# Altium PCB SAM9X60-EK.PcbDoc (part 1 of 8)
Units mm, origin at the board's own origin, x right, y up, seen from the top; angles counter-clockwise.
Board outline 150 x 125 mm, 4 copper layers (L1 - Top Layer, L2 - GND, L3 - PWR, L4 - Bottom Layer), stack 1.52 mm thick; 566 components, 500 nets, 2132 pads, 1038 vias.
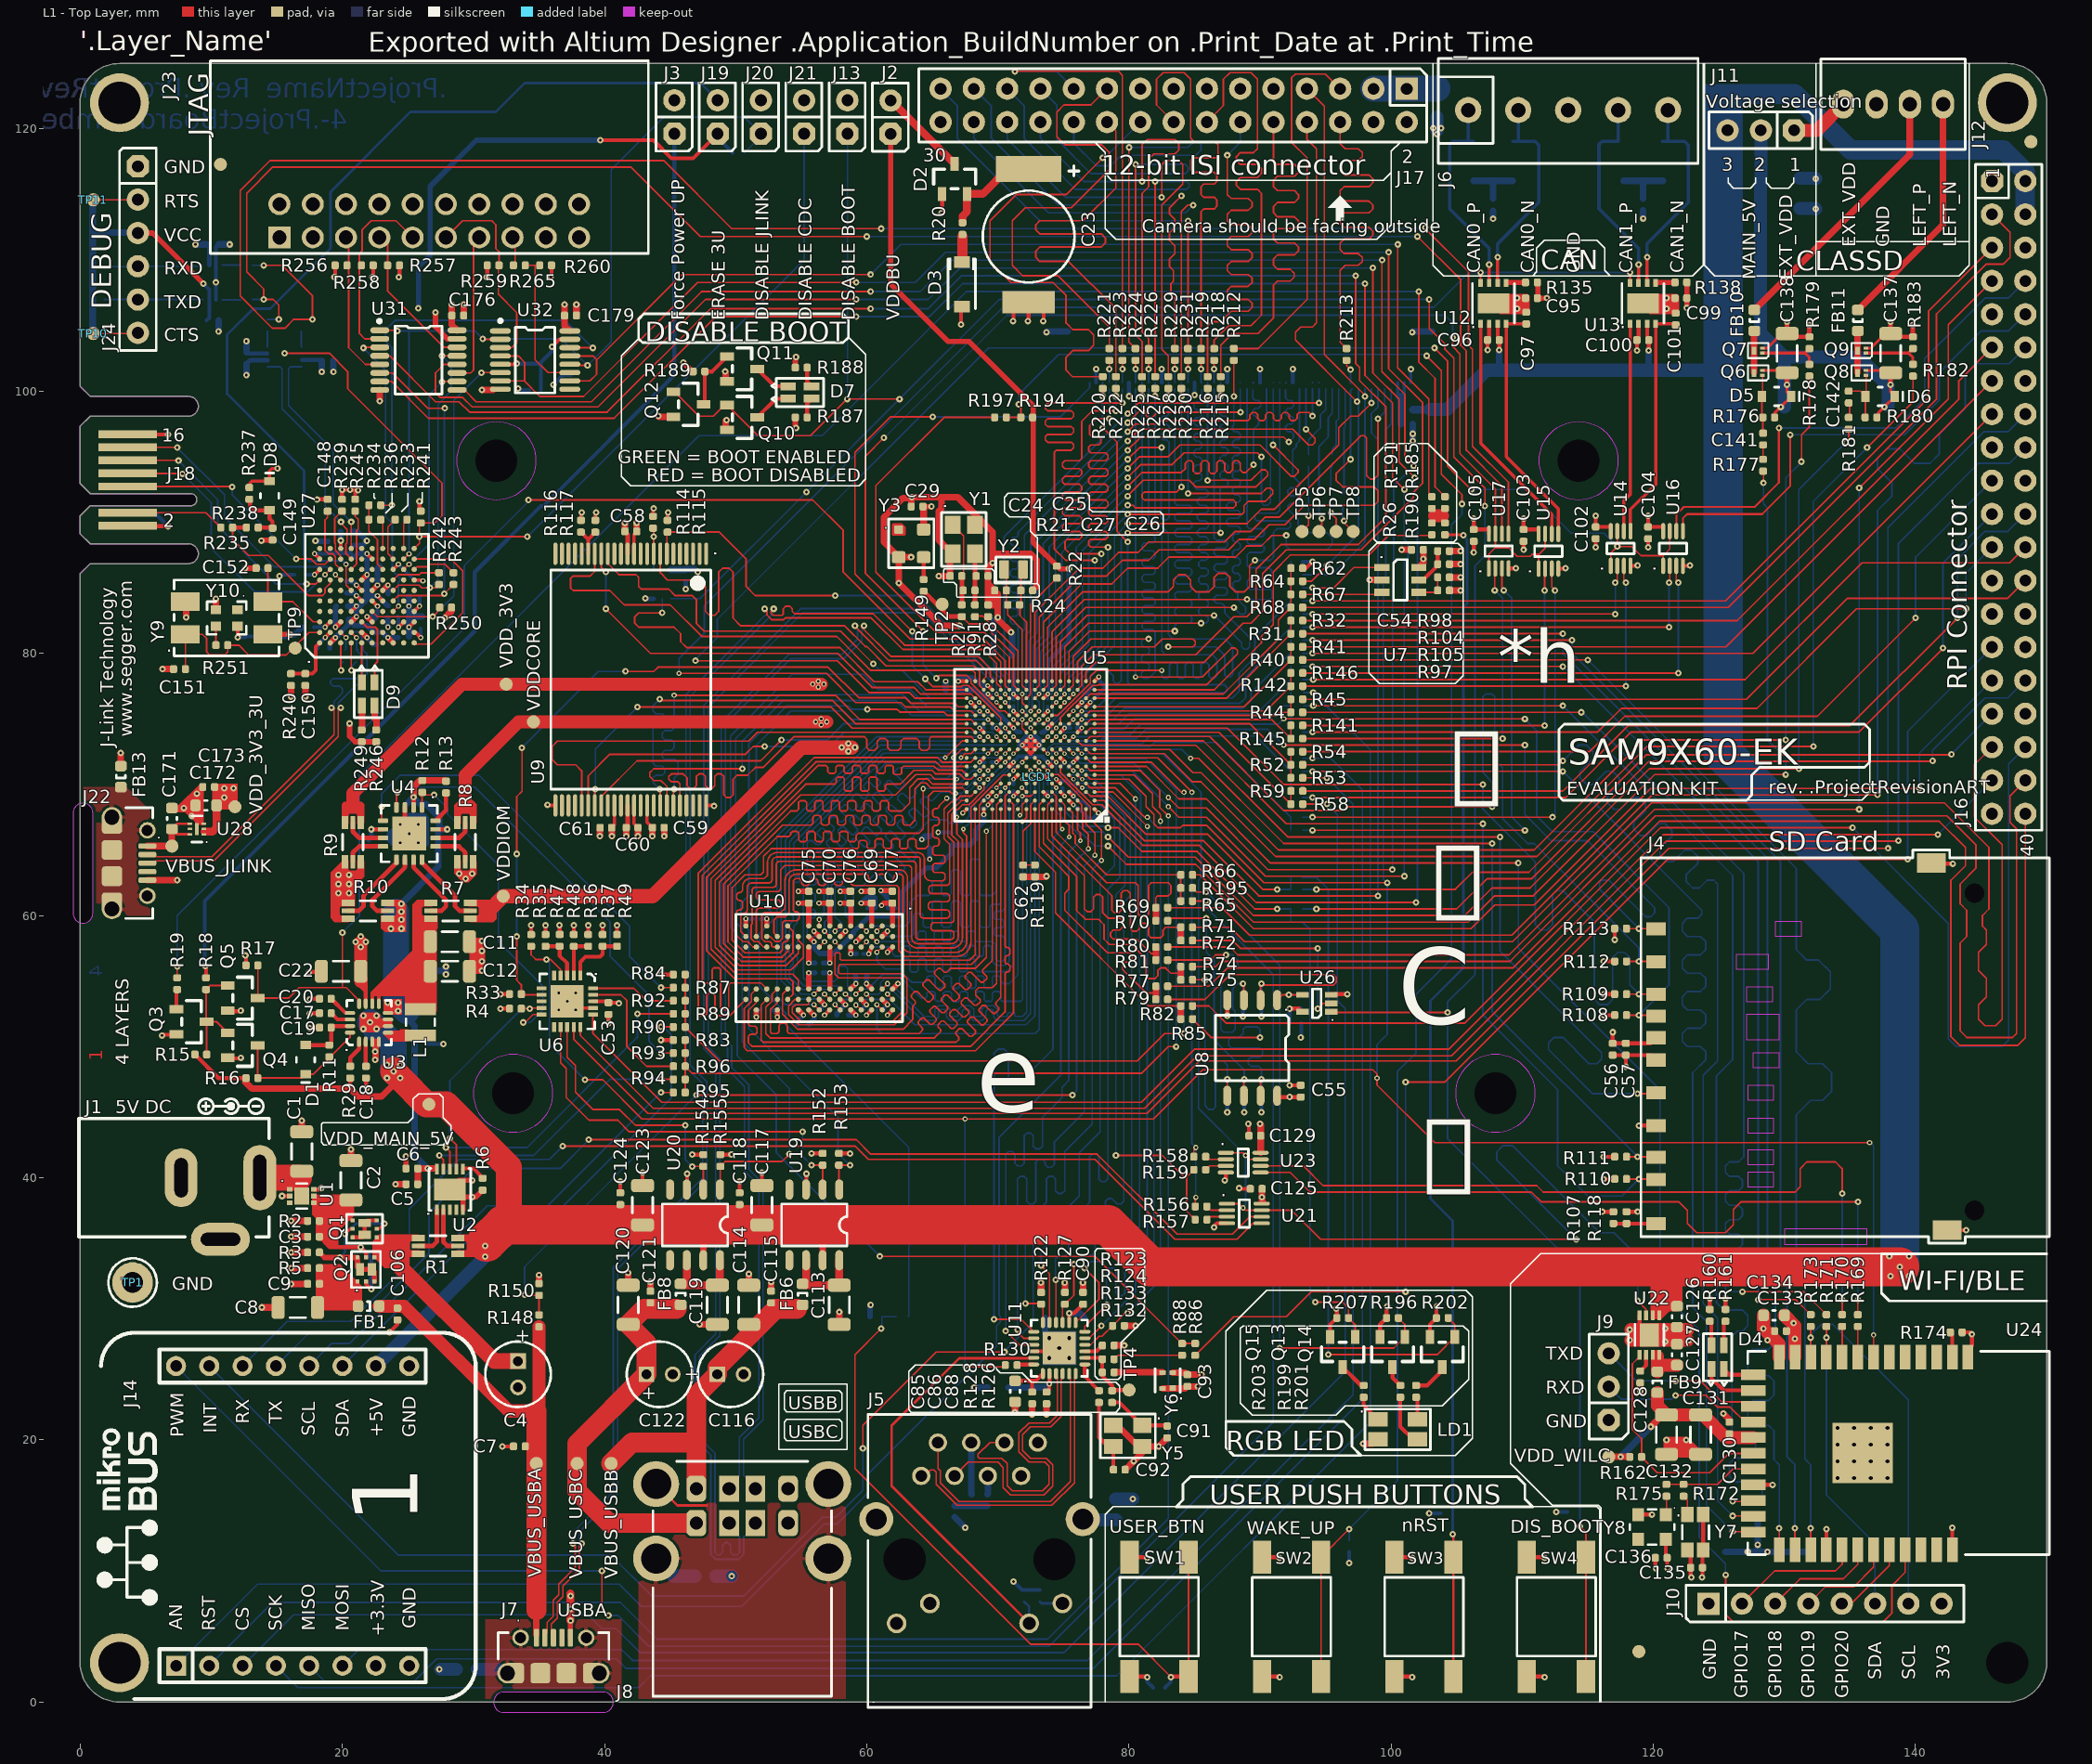
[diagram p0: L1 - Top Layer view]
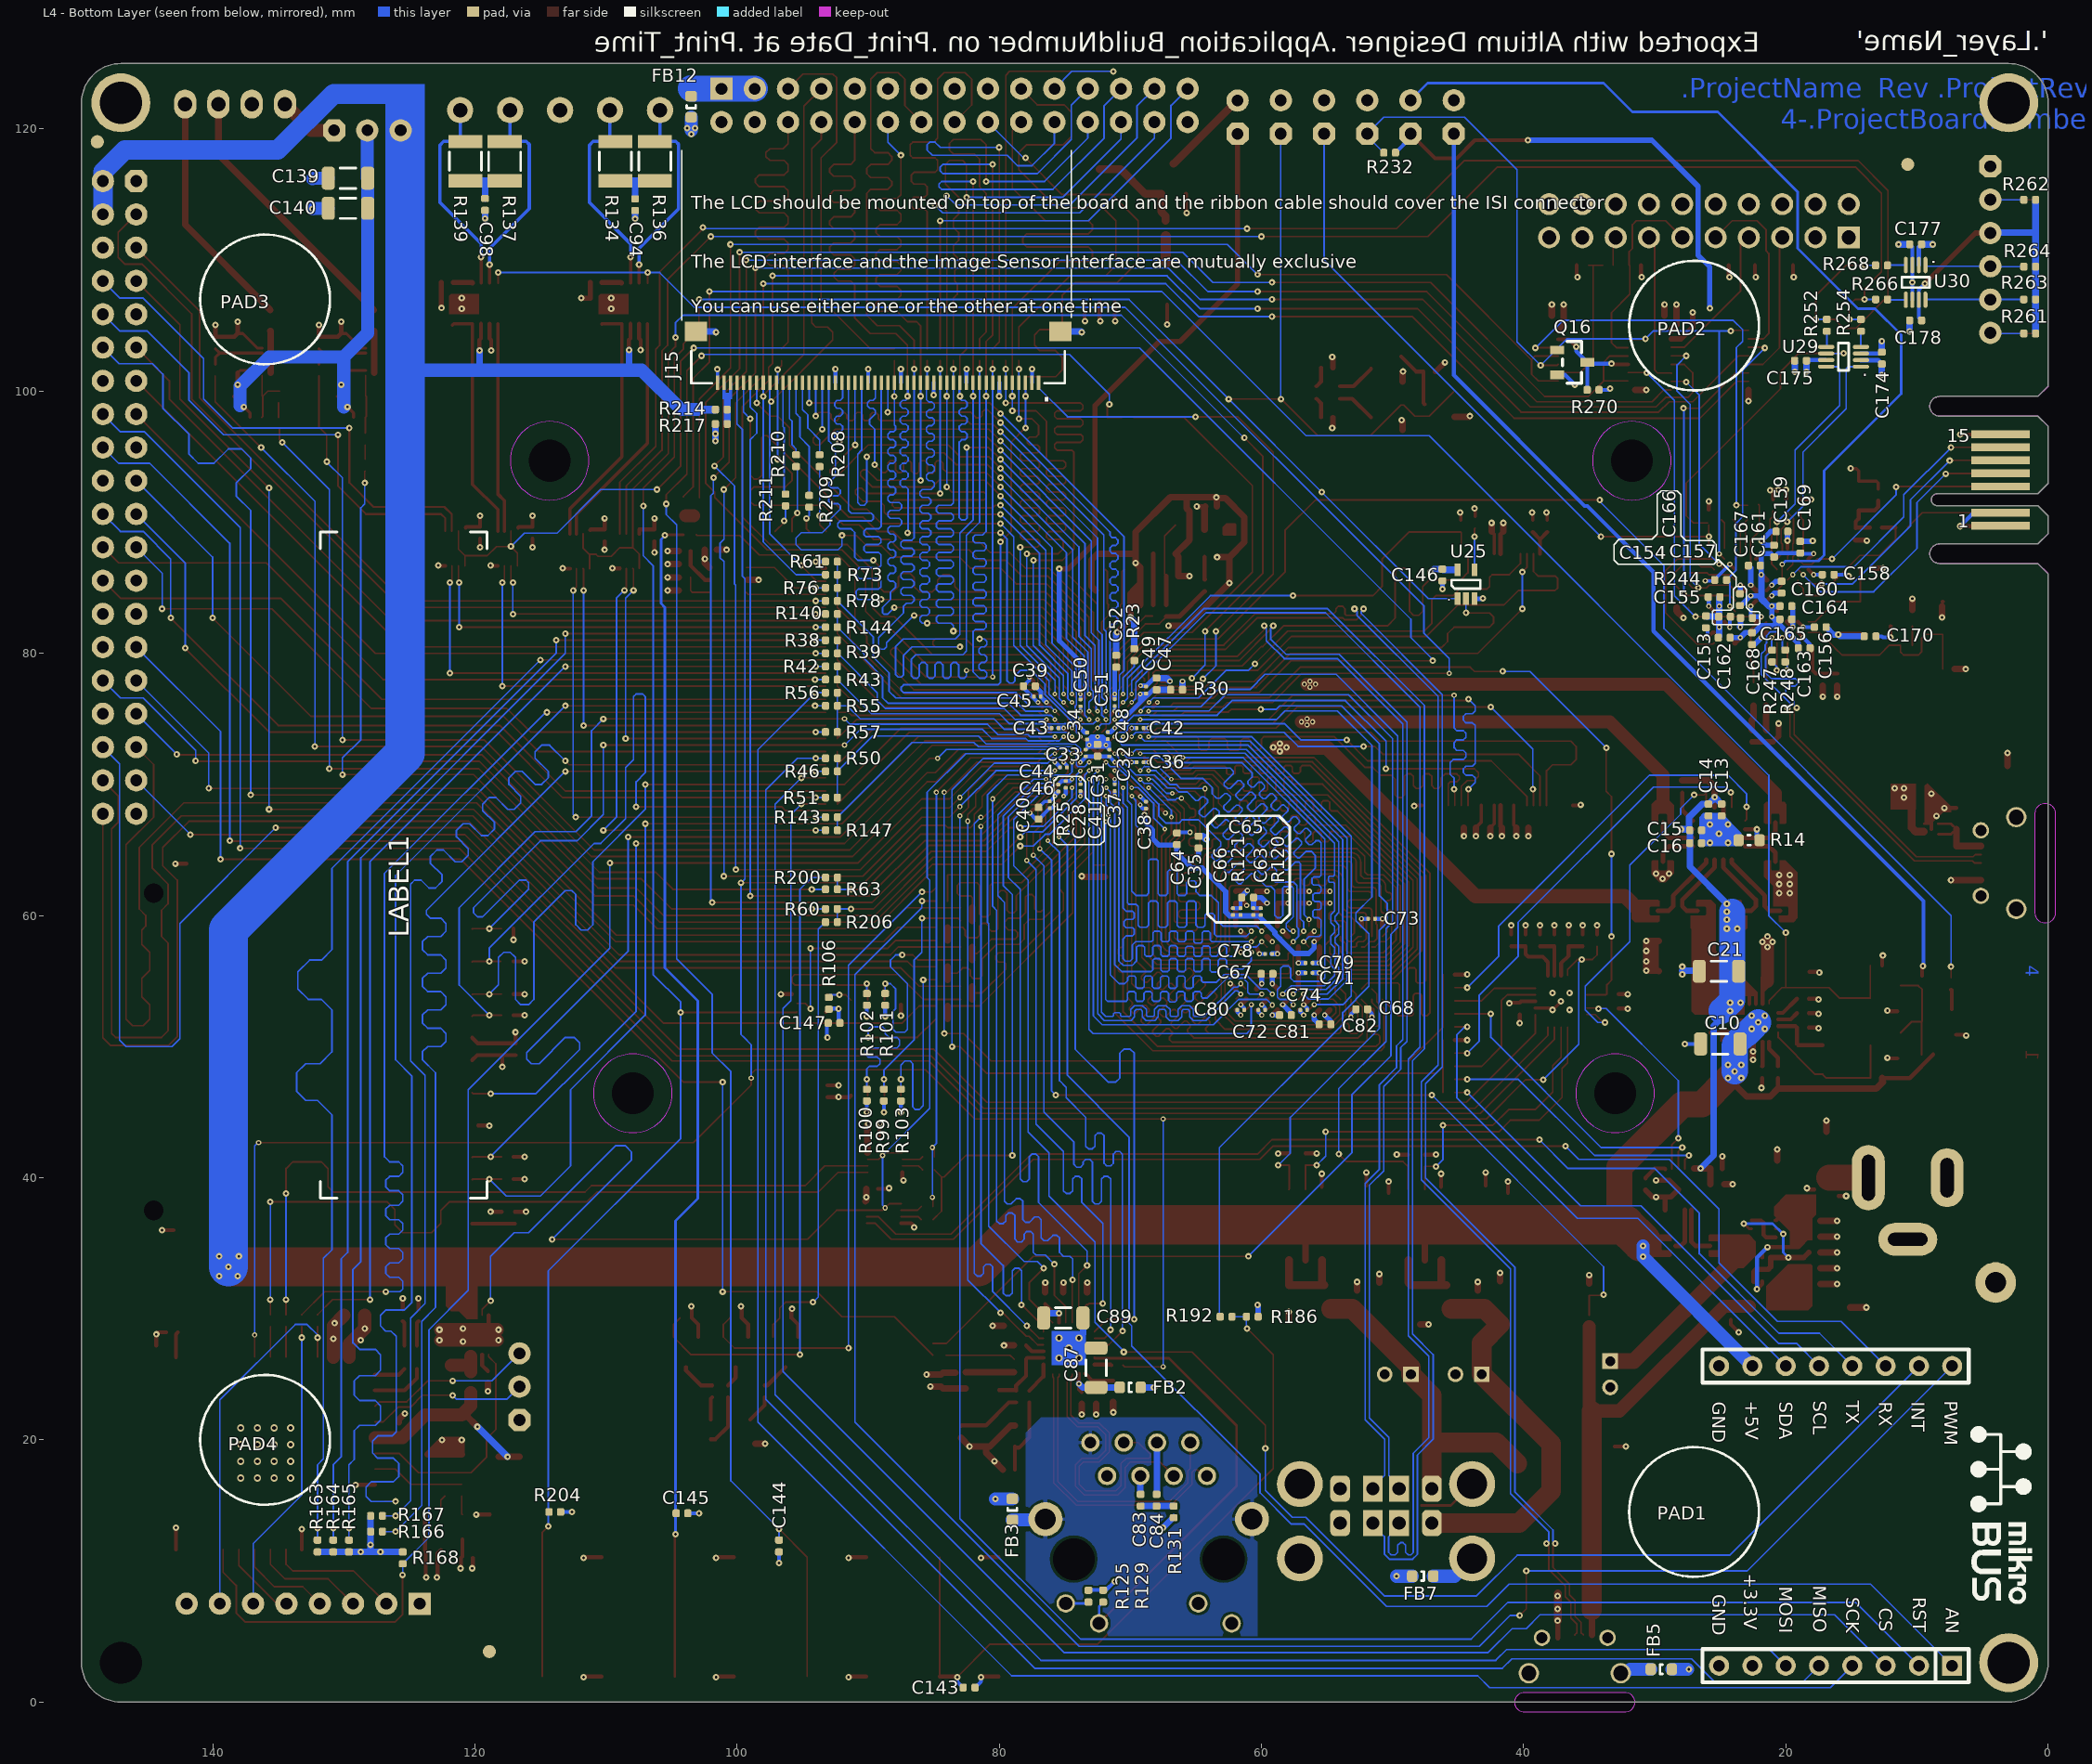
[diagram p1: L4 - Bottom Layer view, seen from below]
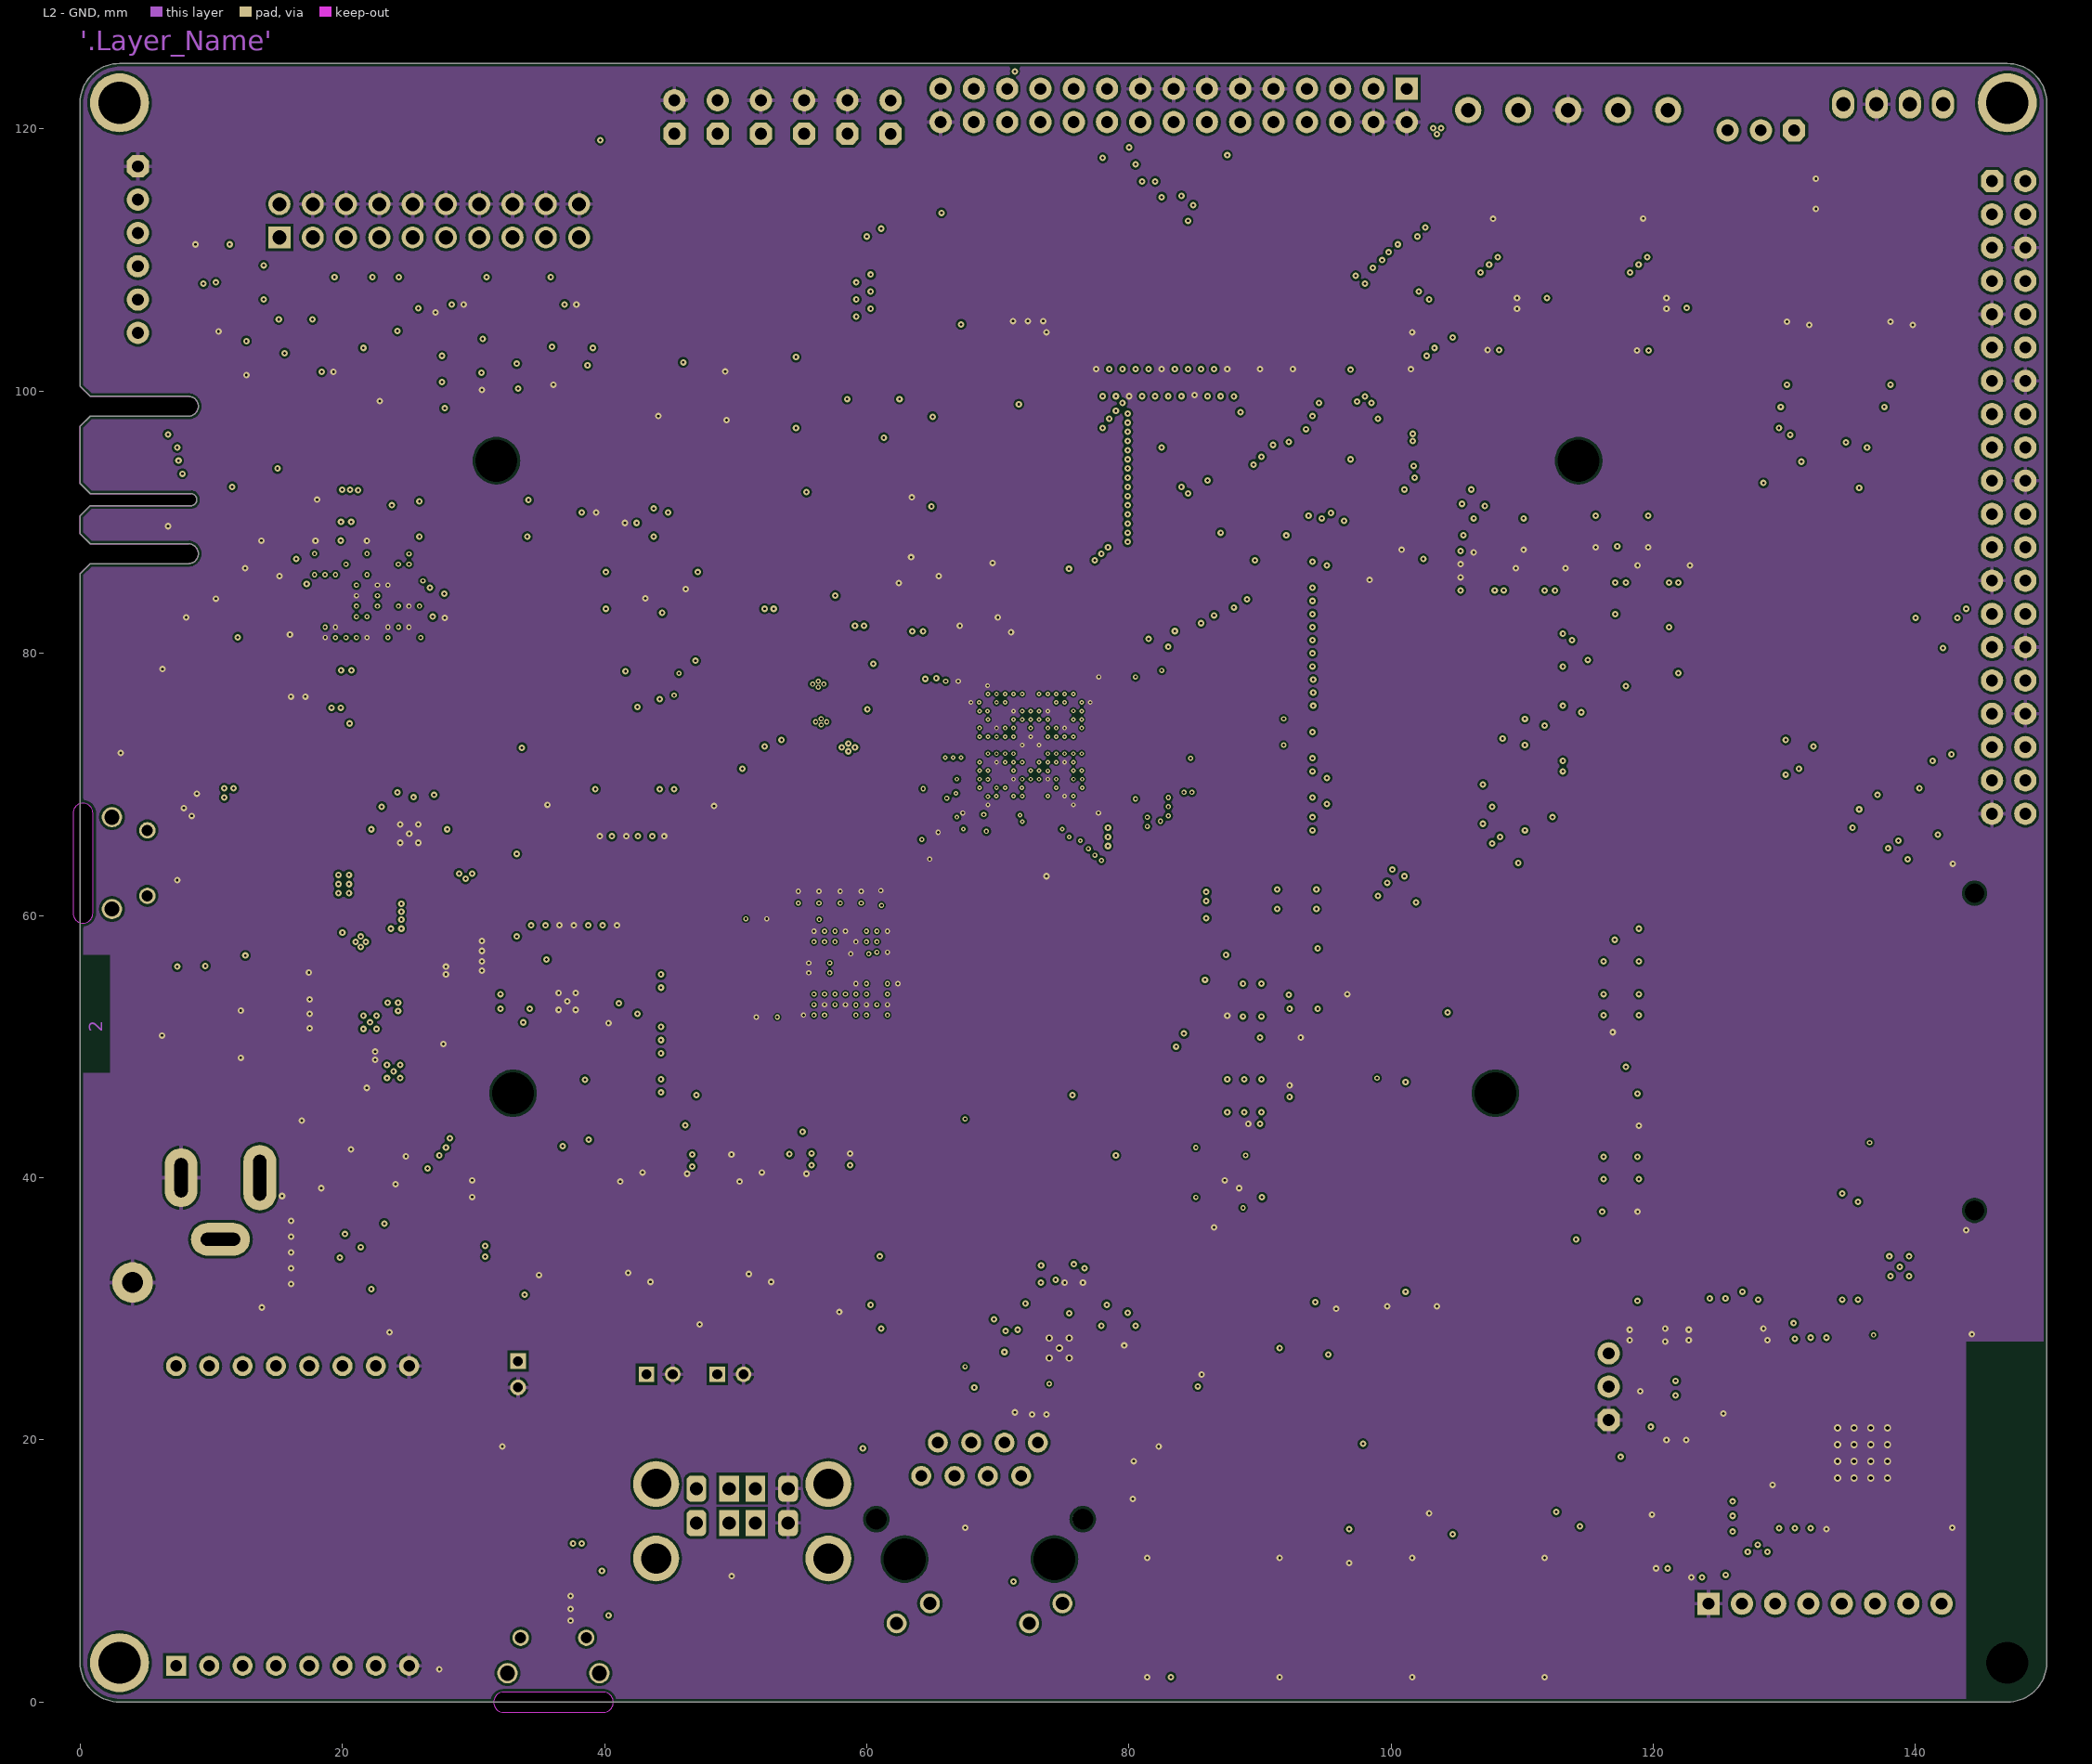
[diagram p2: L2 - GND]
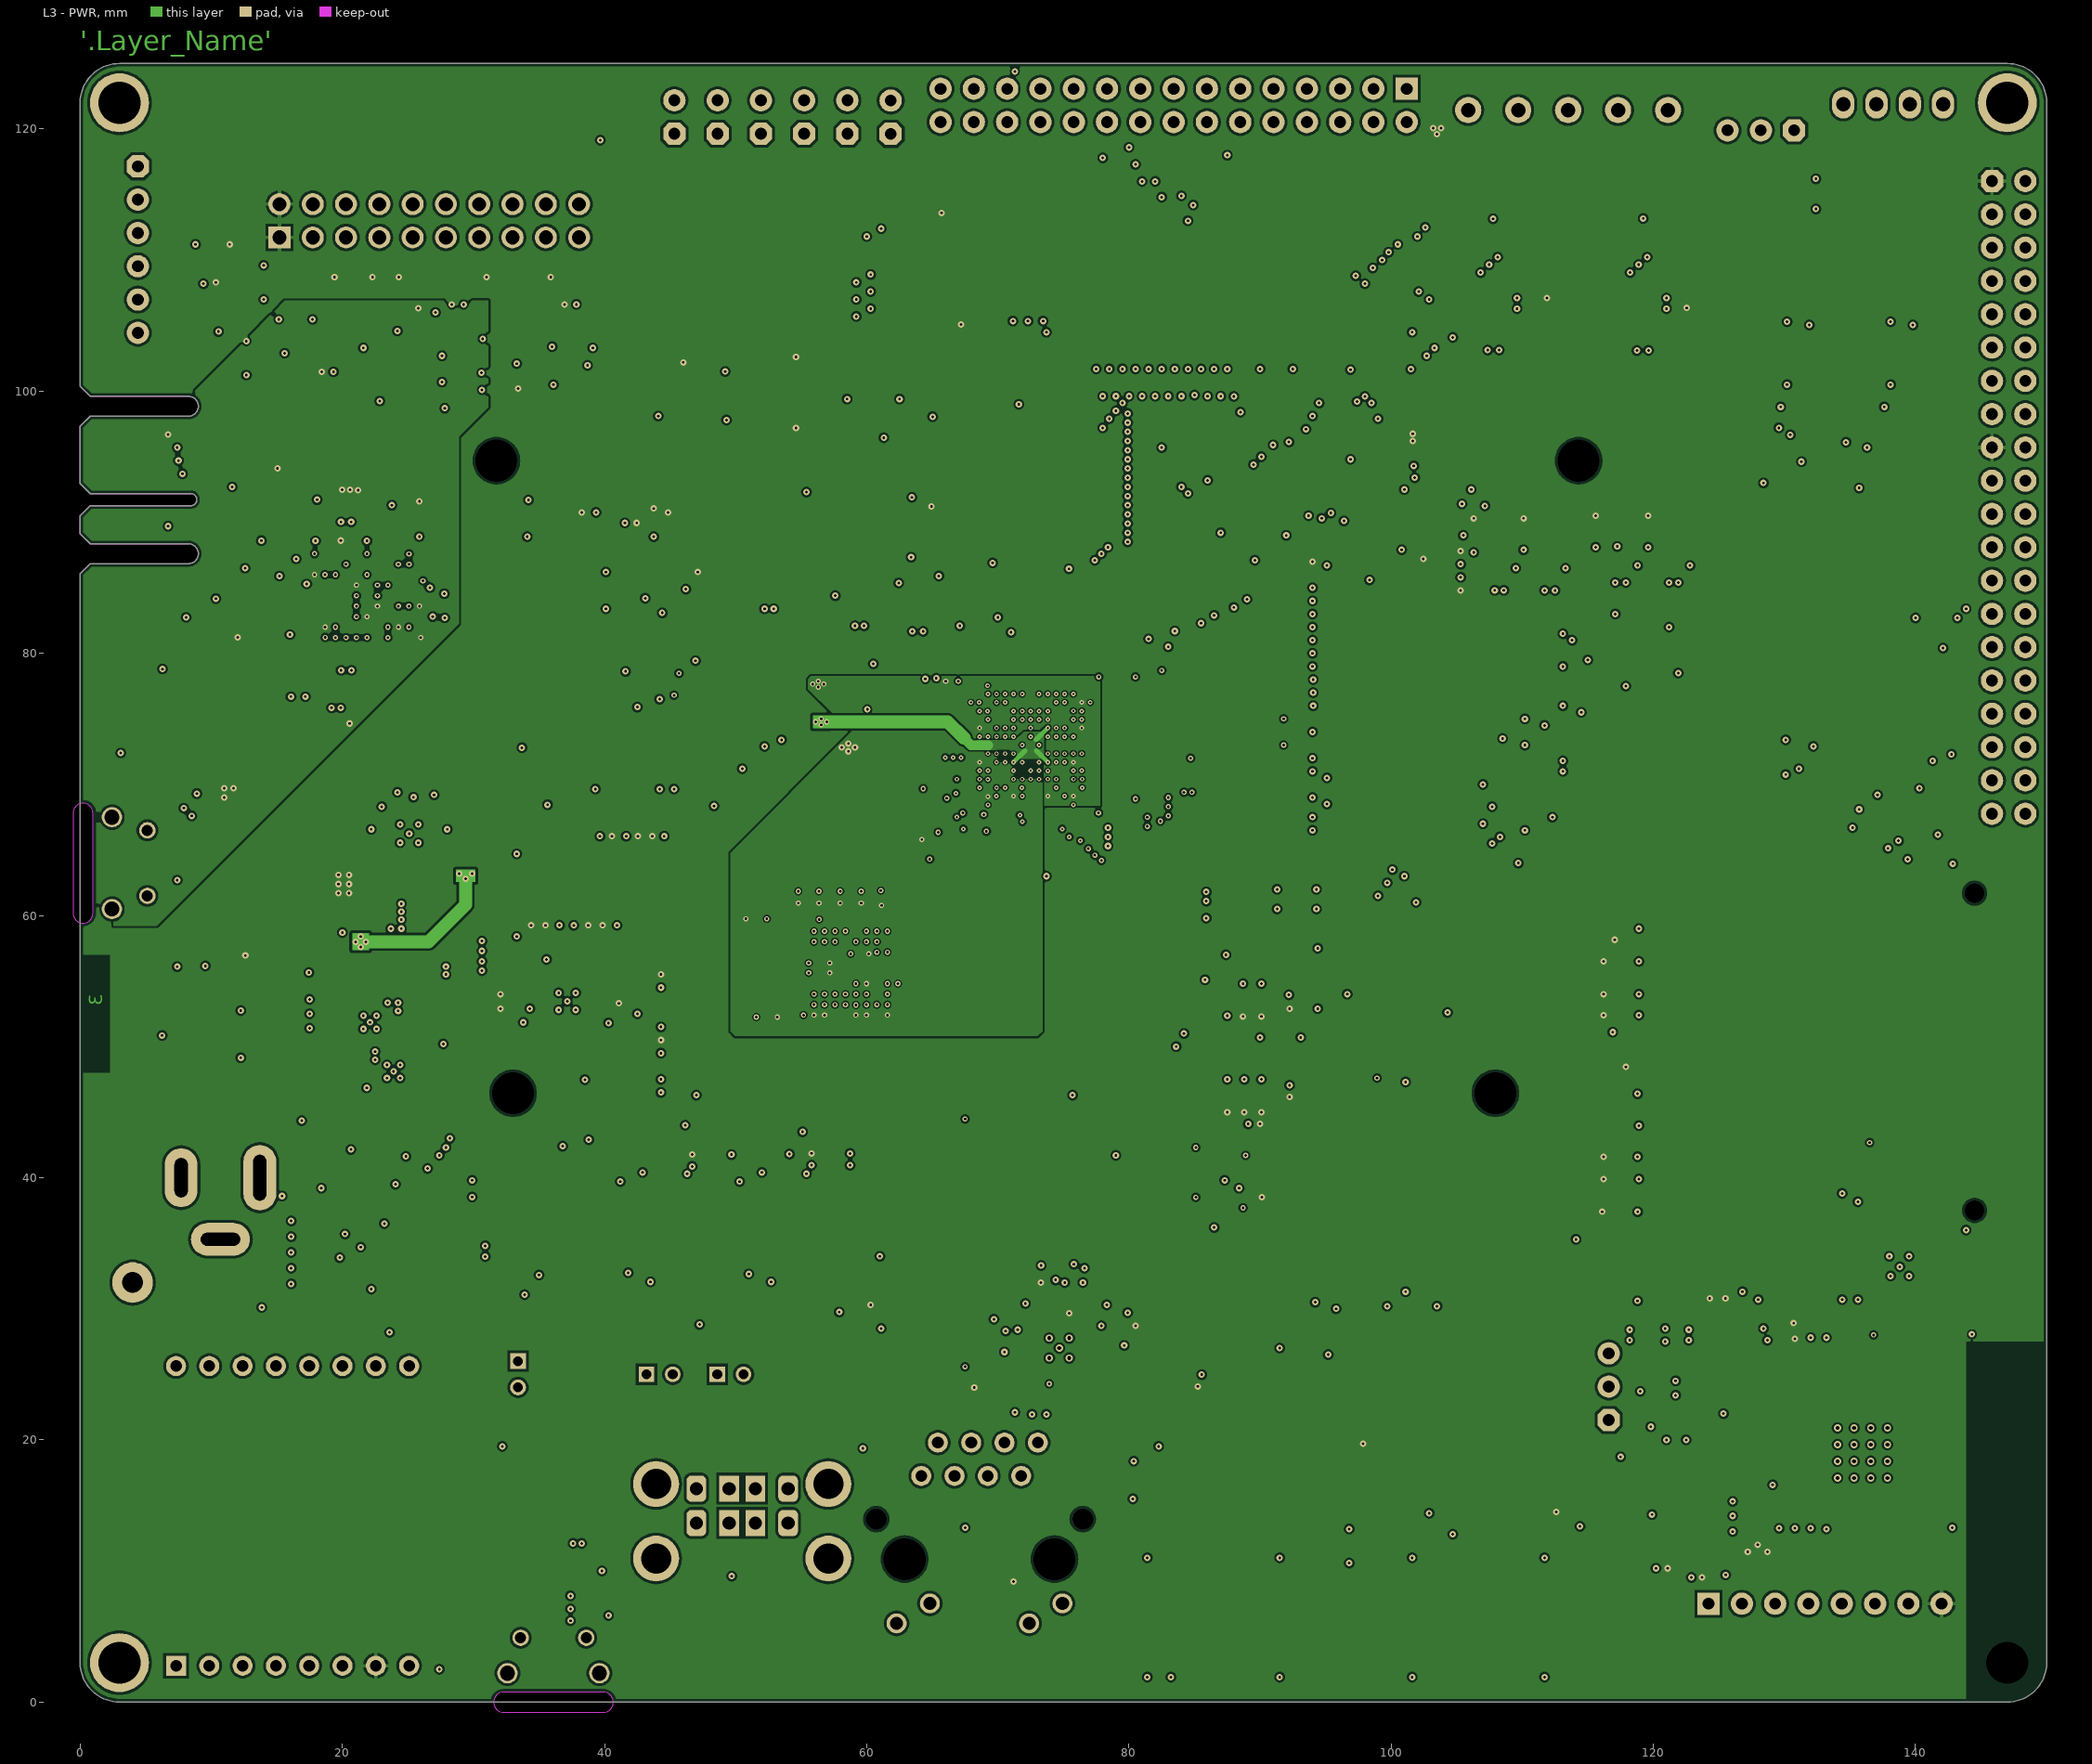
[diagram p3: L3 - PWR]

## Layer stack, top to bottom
Top Solder: solder mask 0.02, Solder Resist, Dk 3.5
L1 - Top Layer: signal copper 0.035
Dielectric 1: prepreg 0.09, Dk 4.2
L2 - GND: signal copper 0.035
Dielectric 2: core 1.2, FR-4, Dk 4.2
L3 - PWR: signal copper 0.035
Dielectric 3: prepreg 0.09, Dk 4.2
L4 - Bottom Layer: signal copper 0.035
Bottom Solder: solder mask 0.02, Solder Resist, Dk 3.5

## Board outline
0,3 0,86.075 0.775,86.85 8.265,86.85 ccw(c8.265,87.6) 8.265,88.35 0.775,88.35 0,89.125 0,90.493 0.775,91.268 8.443,91.268 ccw(c8.443,91.725) 8.443,92.182 0.775,92.182 0,92.957 0,97.325 0.775,98.1 8.265,98.1 ccw(c8.265,98.85) 8.265,99.6 0.775,99.6 0,100.375 0,122 cw(c3,122) 3,125 147,125 cw(c147,122) 150,122 150,3 cw(c147,3) 147,0 3,0 cw(c3,3)

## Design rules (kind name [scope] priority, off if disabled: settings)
AssemblyTestPointUsage [All] p1 off:
AssemblyTestpoint [All] p1 off: testpointundercomponent=TRUE minsize=1.016 maxsize=2.54 preferedsize=1.524 minholesize=0 maxholesize=1.016 preferedholesize=0.813 testpointgrid=0.025 usegrid=TRUE gridtolerance=0 allowsidetop=TRUE allowsidebottom=TRUE
BoardOutlineClearance BoardOutlineClearance_Overlay [OnLayer('Top Overlay','Bottom Overlay')] p1: gap=0.2 ignorepadtopadclearanceinfootprint=FALSE
BoardOutlineClearance [All] p2: gap=0.25 ignorepadtopadclearanceinfootprint=FALSE
Clearance PadToVia [IsPad  AND NOT HasFootprint('MODULE ATWILC3000-MR110CA')  AND NOT HasFootprint('QFN-24_4X4')  AND NOT HasFootprint('QFN-20_4x4')  AND NOT HasFootprint('DFN-10_2.5x2.5_EP1.2x1.9') and NOT HasFootprint('UQFN-16_4X4_EP2.6X2.6') vs IsVia] p1: gap=0.065 ignorepadtopadclearanceinfootprint=TRUE
Clearance U4 [WithinRoom('Room-U4') or TouchesRoom('Room-U4')] p2: gap=0.1 ignorepadtopadclearanceinfootprint=TRUE except(0.15: Arc-Fill Arc-Poly Arc-Region Track-Fill Track-Poly Track-Region SMDPad-Fill SMDPad-Poly SMDPad-Region THPad-Fill THPad-Poly THPad-Region Fill-Fill Fill-Poly Fill-Region Poly-Poly Poly-Region Region-Region)
Clearance U5 [WithinRoom('Room-U5') or TouchesRoom('Room-U5')] p3: gap=0.1 ignorepadtopadclearanceinfootprint=TRUE except(0.15: Arc-Fill Arc-Poly Arc-Region Track-Fill Track-Poly Track-Region SMDPad-Fill SMDPad-Poly SMDPad-Region THPad-Fill THPad-Poly THPad-Region Fill-Fill Fill-Poly Fill-Region Poly-Poly Poly-Region Region-Region)
Clearance [All] p4: gap=0.15 ignorepadtopadclearanceinfootprint=TRUE except(0.125: Arc-Arc Arc-Track Arc-SMDPad Arc-Via Track-Track Track-SMDPad Track-Via; 0.17: Arc-Fill Arc-Poly Arc-Region Track-Fill Track-Poly Track-Region SMDPad-Fill SMDPad-Poly SMDPad-Region; 0.2: Arc-Hole Track-Hole SMDPad-Hole THPad-Fill THPad-Poly THPad-Region THPad-Hole Via-Hole Fill-Fill Fill-Poly Fill-Region Fill-Hole Poly-Poly Poly-Region Poly-Hole Region-Region Region-Hole Text-Hole)
ComponentClearance Ignore_Y9-Y10 [InComponent('Y9') vs InComponent('Y10')] p1: gap=0 collisioncheckmode=3 verticalgap=0 showdistances=TRUE
ComponentClearance Ignore_Y9-R245 [InComponent('Y9') vs InComponent('R251')] p2: gap=0 collisioncheckmode=3 verticalgap=0 showdistances=TRUE
ComponentClearance [All] p3: gap=0.2 collisioncheckmode=3 verticalgap=0.2 showdistances=TRUE
DiffPairsRouting 90-DiffPairsRouting [InDifferentialPairClass('DIFF90')] p1: maxlimit=0.2 minlimit=0.2 mostfreqgap=0.2 toplayer_minwidth=0.1 toplayer_maxwidth=0.125 toplayer_prefwidth=0.125 midlayer1_minwidth=0.1 midlayer1_maxwidth=0.125 midlayer1_prefwidth=0.125 midlayer2_minwidth=0.1 midlayer2_maxwidth=0.125 midlayer2_prefwidth=0.125 bottomlayer_minwidth=0.1 bottomlayer_maxwidth=0.125 bottomlayer_prefwidth=0.125 maxuncoupledlength=12.7 // 90 ohm differential impedance
DiffPairsRouting 100-DiffPairsRouting [InDifferentialPairClass('DIFF100')] p2: maxlimit=0.2 minlimit=0.2 mostfreqgap=0.2 toplayer_minwidth=0.1 toplayer_maxwidth=0.1 toplayer_prefwidth=0.1 midlayer1_minwidth=0.1 midlayer1_maxwidth=0.1 midlayer1_prefwidth=0.1 midlayer2_minwidth=0.1 midlayer2_maxwidth=0.1 midlayer2_prefwidth=0.1 bottomlayer_minwidth=0.1 bottomlayer_maxwidth=0.1 bottomlayer_prefwidth=0.1 maxuncoupledlength=12.7 // 100 ohm differential impedance
DiffPairsRouting [All] p3: maxlimit=0.2 minlimit=0.2 mostfreqgap=0.2 toplayer_minwidth=0.1 toplayer_maxwidth=0.1 toplayer_prefwidth=0.1 midlayer1_minwidth=0.1 midlayer1_maxwidth=0.1 midlayer1_prefwidth=0.1 midlayer2_minwidth=0.1 midlayer2_maxwidth=0.1 midlayer2_prefwidth=0.1 bottomlayer_minwidth=0.1 bottomlayer_maxwidth=0.1 bottomlayer_prefwidth=0.1 maxuncoupledlength=12.7 // 100 ohm differential impedance
FabricationTestPointUsage TestPointUsage [All] p1 off: valid=0 allowmultiple=FALSE
FabricationTestpoint Testpoint [All] p1 off: side=3 testpointundercomponent=TRUE minsize=1.016 maxsize=2.54 preferedsize=1.524 minholesize=0 maxholesize=1.016 preferedholesize=0.813 testpointgrid=0.025 allowsidetop=TRUE allowsidebottom=TRUE usegrid=TRUE gridtolerance=0
HoleSize [All] p1: absolutevalues=TRUE maxlimit=6 minlimit=0.15 maxpercent=80.000 minpercent=20.000
HoleToHoleClearance [All] p1: gap=0.25 allowstackedmicrovias=FALSE
MatchedLengths "Schematic Matched Net Lengths_2" [InNetClass('DIFF90')] p1: tolerance=0.254 checknetsindiffpair=TRUE checkdiffpairvsdiffpair=FALSE checkxsignals=FALSE checkothers=FALSE
MatchedLengths "Schematic Matched Net Lengths" [InNetClass('DIFF100')] p2: tolerance=0.254 checknetsindiffpair=TRUE checkdiffpairvsdiffpair=FALSE checkxsignals=FALSE checkothers=FALSE
MatchedLengths NAND [InxSignalClass('NAND FLASH')] p3: tolerance=0.25 checknetsindiffpair=FALSE checkdiffpairvsdiffpair=TRUE checkxsignals=TRUE checkothers=TRUE
MatchedLengths "Schematic Matched Net Lengths_3" [InNetClass('SDMMC-0')] p4 off: tolerance=0.25 checknetsindiffpair=FALSE checkdiffpairvsdiffpair=TRUE checkxsignals=TRUE checkothers=TRUE
MatchedLengths "Schematic Matched Net Lengths_8" [InNetClass('SDMMC-1')] p5 off: tolerance=0.25 checknetsindiffpair=FALSE checkdiffpairvsdiffpair=TRUE checkxsignals=TRUE checkothers=TRUE
MatchedLengths "Schematic Matched Net Lengths_1" [InNetClass('Q-SPI')] p6 off: tolerance=0.25 checknetsindiffpair=FALSE checkdiffpairvsdiffpair=TRUE checkxsignals=TRUE checkothers=TRUE
MatchedLengths "Schematic Matched Net Lengths_5" [InNetClass('LCD-DATA')] p7 off: tolerance=0.5 checknetsindiffpair=FALSE checkdiffpairvsdiffpair=TRUE checkxsignals=TRUE checkothers=TRUE
MatchedLengths DDR_ADDR [InNetClass('DDR-ADD-CTL')] p8: tolerance=0.25 checknetsindiffpair=FALSE checkdiffpairvsdiffpair=TRUE checkxsignals=TRUE checkothers=TRUE
MatchedLengths DDR_LANE1 [InNetClass('DDR-LANE1')] p9: tolerance=0.25 checknetsindiffpair=FALSE checkdiffpairvsdiffpair=TRUE checkxsignals=TRUE checkothers=TRUE
MatchedLengths DDR_LANE0 [InNetClass('DDR-LANE0')] p10: tolerance=0.25 checknetsindiffpair=FALSE checkdiffpairvsdiffpair=TRUE checkxsignals=TRUE checkothers=TRUE
MatchedLengths LCD-xSignal [InxSignalClass('LCD')] p11: tolerance=0.5 checknetsindiffpair=FALSE checkdiffpairvsdiffpair=TRUE checkxsignals=TRUE checkothers=TRUE
MatchedLengths "NAND Flash" [InNetClass('NAND-Flash')] p12 off: tolerance=0.25 checknetsindiffpair=FALSE checkdiffpairvsdiffpair=TRUE checkxsignals=TRUE checkothers=TRUE
MatchedLengths ETH-RMII [InNetClass('ETH-RMII')] p13: tolerance=0.5 checknetsindiffpair=FALSE checkdiffpairvsdiffpair=TRUE checkxsignals=TRUE checkothers=TRUE
MatchedLengths QSPI [InxSignalClass('QSPI-MEMORY')] p14: tolerance=0.25 checknetsindiffpair=FALSE checkdiffpairvsdiffpair=TRUE checkxsignals=TRUE checkothers=TRUE
MinimumAnnularRing [All] p1: minimumring=0.1
MinimumSolderMaskSliver [All and not HasFootprint('DFN-6_2x1.6_EP0.4x0.35') and Not HasFootprint('RES_C_CAV_0603x4') and Not HasFootprint('RES_C_1206_SHUNT') and Not HasFootprint('DFN-6_1.2X1.2')] p1: minsoldermaskwidth=0.1
PlaneClearance [All] p1 off: clearance=0.508
PlaneConnect [All] p1 off: planeconnectstyle=Relief reliefexpansion=0.3 reliefentries=4 reliefconductorwidth=0.25 reliefairgap=0.25
PolygonConnect [All] p1: thpad.connectstyle=Relief thpad.reliefconductorwidth=0.3 thpad.reliefentries=4 thpad.polygonreliefangle="90 Angle" thpad.airgapwidth=0.2 smdpad.connectstyle=Direct smdpad.reliefconductorwidth=0.3 smdpad.reliefentries=4 smdpad.polygonreliefangle="90 Angle" smdpad.airgapwidth=0.2 via.connectstyle=Direct via.reliefconductorwidth=0.3 via.reliefentries=4 via.polygonreliefangle="90 Angle" via.airgapwidth=0.25
RoomDefinition Room-U5 [False] p1: confinementstyle=ConfineIn formatcopy=TRUE lockcomponents=FALSE outline 49.85,63 62.925,63 62.925,51.7 49.85,51.7
RoomDefinition Room-U4 [False] p2: confinementstyle=ConfineIn formatcopy=TRUE lockcomponents=FALSE outline 67.5,78 77.5,78 77.5,68.025 67.5,68.025
RoutingCorners [All] p1: cornerstyle=45-Degree minsetback=2.5 maxsetback=2.5
RoutingVias [All] p1: holewidth=0.2 width=0.5 viastyle="Through Hole" minholewidth=0.15 minwidth=0.35 maxholewidth=0.2 maxwidth=0.5
ShortCircuit ShortCircuit_Y3 [HasFootprint('CDFN-4_3.2X2.5')] p1: allowed=TRUE
ShortCircuit [All] p2: allowed=FALSE
SilkToSilkClearance [All] p1: silktosilkclearance=0.15
SilkToSolderMaskClearance SilkscreenOverComponentPads [IsPad] p1: minsilkscreentomaskgap=0.15 clearancetoexposedcopper=TRUE
SolderMaskExpansion SolderMaskExpansion_via [IsVia] p1: expansion=-1 istentingtop=FALSE
SolderMaskExpansion [All] p2: expansion=0.05 istentingtop=FALSE
Width [All] p1: maxlimit=5 minlimit=0.1 preferedwidth=0.15
15 further rules are at their usual default settings.

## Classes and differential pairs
net class SDMMC-1: SDMMC1_WILC3000_CK_PA13 SDMMC1_WILC3000_CMD_PA12 SDMMC1_WILC3000_DAT0_PA11 SDMMC1_WILC3000_DAT1_PA02 SDMMC1_WILC3000_DAT2_PA03 SDMMC1_WILC3000_DAT3_PA04
net class Q-SPI: QSPI_IO0_PB21 QSPI_IO1_PB22 QSPI_IO2_PB23 QSPI_IO3_PB24 QSPI_SCK_PB19
differential pair class DIFF100: DDR_CLK DDR_DQS0 DDR_DQS1 ETH_RX ETH_TX
differential pair class DIFF90: JLINK_USBFS JLINK_USBHS USBA USBB USBC
net class DIFF100: DDR_CLK_N DDR_CLK_P DDR_DQS0_N DDR_DQS0_P DDR_DQS1_N DDR_DQS1_P ETH_RX_N ETH_RX_P ETH_TX_N ETH_TX_P
net class DDR-LANE1: DDR_D8 DDR_D9 DDR_D10 DDR_D11 DDR_D12 DDR_D13 DDR_D14 DDR_D15 DDR_DQM1 DDR_DQS1_N DDR_DQS1_P
net class DDR-LANE0: DDR_D0 DDR_D1 DDR_D2 DDR_D3 DDR_D4 DDR_D5 DDR_D6 DDR_D7 DDR_DQM0 DDR_DQS0_N DDR_DQS0_P
net class DDR-ADD-CTL: DDR_A2 DDR_A3 DDR_A4 DDR_A5 DDR_A6 DDR_A7 DDR_A8 DDR_A9 DDR_A10 DDR_A11 DDR_A13 DDR_A14 DDR_A15 DDR_A16 DDR_A17 DDR_A18 DDR_CAS DDR_CKE DDR_CLK_N DDR_CLK_P DDR_CS DDR_RAS DDR_SDA10 DDR_WE
net class SDMMC-0: SDMMC0_CD_PA23 SDMMC0_CLK_PA17 SDMMC0_CMD_PA16 SDMMC0_DAT0_PA15 SDMMC0_DAT1_PA18 SDMMC0_DAT2_PA19 SDMMC0_DAT3_PA20
net class LCD-DATA: LCD_D0_ISI_D0_PC00 LCD_D1_ISI_D1_PC01 LCD_D2_ISI_D2_PC02 LCD_D3_ISI_D3_PC03 LCD_D4_ISI_D4_PC04 LCD_D5_ISI_D5_PC05 LCD_D6_ISI_D6_PC06 LCD_D7_ISI_D7_PC07 LCD_D8_ISI_D8_PC08 LCD_D9_ISI_D9_PC09 LCD_D10_ISI_D10_PC10 LCD_D11_ISI_D11_PC11 LCD_D12_ISI_PCK_PC12 LCD_D13_ISI_VSYNC_PC13 LCD_D14_ISI_HSYNC_PC14 LCD_D15_ISI_MCK_PC15 LCD_D16_ISI_nRST_PC16 LCD_D17_PC17 LCD_D18_PC18 LCD_D19_PC19 LCD_D20_PC20 LCD_D21_PC21 LCD_D22_PC22 LCD_D23_PC23 LCD_DATA_ENABLE_PC29 LCD_HSYNC/WE_PC28 LCD_IRQ1_PC25 LCD_ISI_ENABLE_PC24 LCD_PCLK_PC30 LCD_PWM_PC26 LCD_VSYNC/CS_PC27
net class NAND-Flash: NAND_ALE_PD02 NAND_CLE_PD03 NAND_IO0_PD06 NAND_IO1_PD07 NAND_IO2_PD08 NAND_IO3_PD09 NAND_IO4_PD10 NAND_IO5_PD11 NAND_IO6_PD12 NAND_IO7_PD13 NAND_nCS_PD04_enabled NAND_nRE_PD00 NAND_nWE_PD01 NAND_RB_PD05
net class DIFF90: JLINK_USBHS_N JLINK_USBHS_P USBA_N USBA_P USBB_N USBB_P USBC_N USBC_P
net class ETH-RMII: ETH0_IRQ_PB08 ETH0_MDC_PB06 ETH0_MDIO_PB05 ETH0_RX0_PB00 ETH0_RX1_PB01 ETH0_RXDV_PB03 ETH0_RXER_PB02 ETH0_TX0_PB09 ETH0_TX1_PB10 ETH0_TXCK_PB04 ETH0_TXEN_PB07
differential pair JLINK_USBHS: +JLINK_USBHS_P -JLINK_USBHS_N
differential pair DDR_CLK: +DDR_CLK_P -DDR_CLK_N
differential pair DDR_DQS0: +DDR_DQS0_P -DDR_DQS0_N
differential pair DDR_DQS1: +DDR_DQS1_P -DDR_DQS1_N
differential pair ETH_RX: +ETH_RX_P -ETH_RX_N
differential pair ETH_TX: +ETH_TX_P -ETH_TX_N
differential pair USBA: +USBA_P -USBA_N
differential pair USBB: +USBB_P -USBB_N
differential pair USBC: +USBC_P -USBC_N

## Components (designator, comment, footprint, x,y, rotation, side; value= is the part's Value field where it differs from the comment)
C1 "Capacitor NP" CAP_C_1206 16.9,42 r90 top value=10uF
C2 "Capacitor NP" CAP_C_1206 20.65,39.8 r90 top value=10uF
C3 "Capacitor NP" CAP_C_0402 17.8,35.5 r180 top value=0.1uF
C4 "Capacitor POL" CAP_RAD_P2D5H12.5 33.4,25 r270 top value=100µF
C5 "Capacitor NP" CAP_C_0402 25.3,39.5 r0 top value=4.7uF
C6 "Capacitor NP" CAP_C_0402 25.3,40.7 r0 top value=0.1uF
C7 "Capacitor NP" CAP_C_0402 33.5,19.5 r180 top value=0.1uF
C8 "Capacitor NP" CAP_C_1206 16.6,30.1 r180 top value=10uF
C9 "Capacitor NP" CAP_C_0402 17.8,31.9 r180 top value=0.1uF
C10 "Capacitor NP" CAP_C_1206 25,50.2 r0 bottom value=10uF
C11 "Capacitor NP" CAP_C_1206 28.2,58 r0 top value=10uF
C12 "Capacitor NP" CAP_C_1206 28.2,55.75 r0 top value=10uF
C13 "Capacitor NP" CAP_C_0402 24.9,68.05 r90 bottom value=4.7uF
C14 "Capacitor NP" CAP_C_0402 25.9,68.05 r90 bottom value=0.1uF
C15 "Capacitor NP" CAP_C_0402 26.875,66.5 r0 bottom value=4.7uF
C16 "Capacitor NP" CAP_C_0402 26.875,65.525 r0 bottom value=0.1uF
C17 "Capacitor NP" CAP_C_0402 18.7,52.55 r180 top value=0.1uF
C18 "Capacitor NP" CAP_C_0402 21.8,48.05 r270 top value=0.1uF
C19 "Capacitor NP" CAP_C_0402 18.7,51.45 r180 top value=0.1uF
C20 "Capacitor NP" CAP_C_0402 18.7,53.65 r180 top value=10nF
C21 "Capacitor NP" CAP_C_1206 25.1,55.75 r0 bottom value=10uF
C22 "Capacitor NP" CAP_C_1206 19.9,55.75 r180 top value=10uF
C23 "Capacitor POL" CAP_AX_P8.3L11.7D6.8H1.8 72.35,111.875 r0 top value=220mF
C24 "Capacitor NP" CAP_C_0402 66.8,85.9 r180 top value=27pF
C25 "Capacitor NP" CAP_C_0402 68.8,85.9 r0 top value=27pF
C26 "Capacitor NP" CAP_C_0402 72.2,84.8 r0 top value=20pF
C27 "Capacitor NP" CAP_C_0402 70.2,84.8 r180 top value=20pF
C28 "Capacitor NP" CAP_C_0201 74.925,70 r90 bottom value=1uF
C29 "Capacitor NP" CAP_C_0402 63.837,91.2 r0 top value=0.1uF
C31 "Capacitor NP" CAP_C_0402 72.5,72.6 r270 bottom value=4.7uF
C32 "Capacitor NP" CAP_C_0201 71.6,72.4 r90 bottom value=0.1uF
C33 "Capacitor NP" CAP_C_0201 73.4,72.4 r90 bottom value=0.1uF
C34 "Capacitor NP" CAP_C_0201 73.3,73.7 r270 bottom value=0.1uF
C35 "Capacitor NP" CAP_C_0402 64.8,65.6 r90 bottom value=4.7uF
C36 "Capacitor NP" CAP_C_0201 69.257,71.696 r0 bottom value=0.1uF
C37 "Capacitor NP" CAP_C_0201 71.2,69.75 r90 bottom value=0.1uF
C38 "Capacitor NP" CAP_C_0201 68.799,68.42 r270 bottom value=0.1uF
C39 "Capacitor NP" CAP_C_0402 77.7,77.5 r180 bottom value=4.7uF
C40 "Capacitor NP" CAP_C_0402 77,67.8 r90 bottom value=4.7uF
C41 "Capacitor NP" CAP_C_0201 73.8,69.75 r90 bottom value=0.1uF
C42 "Capacitor NP" CAP_C_0201 69.25,74.3 r0 bottom value=0.1uF
C43 "Capacitor NP" CAP_C_0201 75.75,74.3 r180 bottom value=0.1uF
C44 "Capacitor NP" CAP_C_0201 75.1,71.3 r180 bottom value=0.1uF
C45 "Capacitor NP" CAP_C_0201 77.1,76.7 r0 bottom value=0.1uF
C46 "Capacitor NP" CAP_C_0201 76.15,68.45 r270 bottom value=0.1uF
C47 "Capacitor NP" CAP_C_0402 68,77.668 r270 bottom value=4.7uF
C48 "Capacitor NP" CAP_C_0201 71.725,73.725 r270 bottom value=0.1uF
C49 "Capacitor NP" CAP_C_0201 68.8,77.2 r90 bottom value=0.1uF
C50 "Capacitor NP" CAP_C_0201 73.8,76.225 r270 bottom value=0.1uF
C51 "Capacitor NP" CAP_C_0201 71.2,76.25 r270 bottom value=0.1uF
C52 "Capacitor NP" CAP_C_0402 71.075,79.4 r90 bottom value=2.2uF
C53 "Capacitor NP" CAP_C_0402 40.3,52.9 r270 top value=0.1uF
C54 "Capacitor NP" CAP_C_0402 102,87.9 r180 top value=0.1uF
C55 "Capacitor NP" CAP_C_0402 93.1,46.6 r90 top value=0.1uF
C56 "Capacitor NP" CAP_C_0402 116.9,49.8 r90 top value=0.1uF
C57 "Capacitor NP" CAP_C_0402 117.9,49.8 r270 top value=4.7uF
C58 "Capacitor NP" CAP_C_0402 42,89.3 r180 top value=0.1uF
C59 "Capacitor NP" CAP_C_0402 44.1,66.7 r0 top value=0.1uF
C60 "Capacitor NP" CAP_C_0402 42.1,66.7 r180 top value=0.1uF
C61 "Capacitor NP" CAP_C_0402 40.1,66.7 r180 top value=0.1uF
C62 "Capacitor NP" CAP_C_0402 71.925,63.4 r90 top value=22pF
C63 "Capacitor NP" CAP_C_0201 60.625,60.3 r90 bottom value=0.1uF
C64 "Capacitor NP" CAP_C_0402 66.45,65.85 r90 bottom value=10nF
C65 "Capacitor NP" CAP_C_0402 61.05,61.375 r180 bottom value=4.7uF
C66 "Capacitor NP" CAP_C_0201 62.175,60.3 r270 bottom value=0.1uF
C67 "Capacitor NP" CAP_C_0402 59.575,55.55 r0 bottom value=4.7uF
C68 "Capacitor NP" CAP_C_0402 52.35,52.85 r0 bottom value=4.7uF
C69 "Capacitor NP" CAP_C_0402 60.375,61.4 r90 top value=0.1uF
C70 "Capacitor NP" CAP_C_0402 57.175,61.4 r90 top value=0.1uF
C71 "Capacitor NP" CAP_C_0201 56.375,55.625 r0 bottom value=0.1uF
C72 "Capacitor NP" CAP_C_0201 59.975,52.8 r0 bottom value=0.1uF
C73 "Capacitor NP" CAP_C_0201 51.6,59.75 r180 bottom value=0.1uF
C74 "Capacitor NP" CAP_C_0201 56.775,52.8 r0 bottom value=0.1uF
C75 "Capacitor NP" CAP_C_0402 55.575,61.4 r90 top value=0.1uF
C76 "Capacitor NP" CAP_C_0402 58.75,61.4 r90 top value=0.1uF
C77 "Capacitor NP" CAP_C_0402 61.95,61.4 r90 top value=0.1uF
C78 "Capacitor NP" CAP_C_0201 59.45,57.075 r0 bottom value=0.1uF
C79 "Capacitor NP" CAP_C_0201 56.375,56.375 r0 bottom value=0.1uF
C80 "Capacitor NP" CAP_C_0201 61.575,52.8 r0 bottom value=0.1uF
C81 "Capacitor NP" CAP_C_0402 58.175,52.4 r0 bottom value=1000pF
C82 "Capacitor NP" CAP_C_0402 55.15,51.7 r0 bottom value=1000pF
C83 "Capacitor NP" CAP_C_0402 69.215,15.4 r270 bottom value=0.1uF
C84 "Capacitor NP" CAP_C_0402 68,15.4 r270 bottom value=0.1uF
C85 "Capacitor NP" CAP_C_0603 71.315,23.7 r270 top value=2.2uF
C86 "Capacitor NP" CAP_C_0402 72.615,23.2 r270 top value=0.1uF
C87 "Capacitor NP" CAP_C_1206 72.615,25.5 r90 bottom value=10uF
C88 "Capacitor NP" CAP_C_0402 73.715,23.2 r270 top value=0.1uF
C89 "Capacitor NP" CAP_C_1206 75.115,29.3 r180 bottom value=10uF
C90 "Capacitor NP" CAP_C_0402 76.5,30.8 r90 top value=0.1uF
C91 "Capacitor NP" CAP_C_0402 82.915,20.6 r270 top value=20pF
C92 "Capacitor NP" CAP_C_0402 79.265,17.725 r0 top value=20pF
C93 "Capacitor NP" CAP_C_0402 84.45,24.525 r90 top value=0.1uF
C94 "Capacitor NP" CAP_C_0402 107.775,114.225 r90 bottom value=4700pF
C95 "Capacitor NP" CAP_C_0402 110.7,107.1 r180 top value=0.1uF
C96 "Capacitor NP" CAP_C_0402 107.8,103.9 r180 top value=0.1uF
C97 "Capacitor NP" CAP_C_0402 110.3,105.575 r270 top value=15pF
C98 "Capacitor NP" CAP_C_0402 119.225,114.25 r90 bottom value=4700pF
C99 "Capacitor NP" CAP_C_0402 122.1,107.1 r180 top value=0.1uF
C100 "Capacitor NP" CAP_C_0402 119.2,103.9 r180 top value=0.1uF
C101 "Capacitor NP" CAP_C_0402 121.7,105.5 r270 top value=15pF
C102 "Capacitor NP" CAP_C_0402 115.6,89.2 r270 top value=0.1uF
C103 "Capacitor NP" CAP_C_0402 110.1,89 r270 top value=0.1uF
C104 "Capacitor NP" CAP_C_0402 119.6,89.2 r270 top value=0.1uF
C105 "Capacitor NP" CAP_C_0402 106.3,89 r270 top value=0.1uF
C106 "Capacitor NP" CAP_C_0402 24.2,29.6 r90 top value=20pF
C113 "Capacitor NP" CAP_C_1206 57.9,30.3 r270 top value=10uF
C114 "Capacitor NP" CAP_C_1206 51,30.3 r90 top value=10uF
C115 "Capacitor NP" CAP_C_0402 52.7,30.9 r90 top value=0.1uF
C116 "Capacitor POL" CAP_RAD_P2D5H12.5 49.6,25 r0 top value=100µF
C117 "Capacitor NP" CAP_C_1206 52,37.9 r90 top value=10uF
C118 "Capacitor NP" CAP_C_0402 50.3,38.4 r90 top value=0.1uF
C119 "Capacitor NP" CAP_C_1206 48.6,30.3 r270 top value=10uF
C120 "Capacitor NP" CAP_C_1206 41.8,30.3 r90 top value=10uF
C121 "Capacitor NP" CAP_C_0402 43.5,30.9 r90 top value=0.1uF
C122 "Capacitor POL" CAP_RAD_P2D5H12.5 44.2,25 r0 top value=100µF
C123 "Capacitor NP" CAP_C_1206 42.9,37.9 r90 top value=10uF
C124 "Capacitor NP" CAP_C_0402 41.2,38.4 r90 top value=0.1uF
C125 "Capacitor NP" CAP_C_0402 89.7,39.15 r180 top value=0.1uF
C126 "Capacitor NP" CAP_C_0603 121.8,29.4 r270 top value=2.2uF
C127 "Capacitor NP" CAP_C_0603 121.8,26.5 r270 top value=2.2uF
C128 "Capacitor NP" CAP_C_0402 119,24.8 r90 top value=1000pF
C129 "Capacitor NP" CAP_C_0402 89.6,43.2 r180 top value=0.1uF
C130 "Capacitor NP" CAP_C_0402 125.8,20.9 r90 top value=0.1uF
C131 "Capacitor NP" CAP_C_1206 123.6,20.4 r270 top value=47uF
C132 "Capacitor NP" CAP_C_1206 121,20.4 r270 top value=47uF
C133 "Capacitor NP" CAP_C_0402 129.7,28.3 r180 top value=0.1uF
C134 "Capacitor NP" CAP_C_0603 129.2,29.5 r0 top value=2.2uF
C135 "Capacitor NP" CAP_C_0402 123.3,10.25 r180 top value=0.1uF
C136 "Capacitor NP" CAP_C_0402 120.6,11 r180 top value=0.1uF
C137 "Capacitor NP" CAP_C_1206 138.1,102.9 r270 top value=10uF
C138 "Capacitor NP" CAP_C_1206 130.2,102.9 r270 top value=10uF
C139 "Capacitor NP" CAP_C_1206 129.675,116.25 r180 bottom value=10uF
C140 "Capacitor NP" CAP_C_1206 129.675,113.95 r180 bottom value=10uF
C141 "Capacitor NP" CAP_C_0402 128.375,96.35 r90 top value=10000pF
C142 "Capacitor NP" CAP_C_0402 134.9,99.55 r90 top value=10000pF
C143 "Capacitor NP" CAP_C_0402 82.3,1.1 r180 bottom value=0.1uF
C144 "Capacitor NP" CAP_C_0402 96.8,11.9 r270 bottom value=0.1uF
C145 "Capacitor NP" CAP_C_0402 104.2,14.4 r180 bottom value=0.1uF
C146 "Capacitor NP" CAP_C_0402 46.2,85.975 r90 bottom value=0.1uF
C147 "Capacitor NP" CAP_C_0402 92.6,51.8 r180 bottom value=0.1uF
C148 "Capacitor NP" CAP_C_0402 18.875,91.3 r270 top value=10nF
C149 "Capacitor NP" CAP_C_0402 14.675,89.1 r90 top value=10nF
C150 "Capacitor NP" CAP_C_0402 17.175,78 r270 top value=10pF
C151 "Capacitor NP" CAP_C_0402 7.575,78.8 r180 top value=8.2pF
C152 "Capacitor NP" CAP_C_0402 13.875,86.5 r180 top value=8.2pF
C153 "Capacitor NP" CAP_C_0402 26.1,82.4 r90 bottom value=0.1uF
C154 "Capacitor NP" CAP_C_0402 24.675,82.8 r180 bottom value=0.1uF
C155 "Capacitor NP" CAP_C_0402 25.475,84.3 r180 bottom value=0.1uF
C156 "Capacitor NP" CAP_C_0402 17.375,82 r0 bottom value=4.7uF
C157 "Capacitor NP" CAP_C_0402 23,82.7 r180 bottom value=0.1uF
C158 "Capacitor NP" CAP_C_0402 16.775,86 r0 bottom value=0.1uF
C159 "Capacitor NP" CAP_C_0402 20.3,89.3 r180 bottom value=0.1uF
C160 "Capacitor NP" CAP_C_0402 20.325,85.05 r90 bottom value=0.1uF
C161 "Capacitor NP" CAP_C_0402 20.9,87.8 r270 bottom value=4.7uF
C162 "Capacitor NP" CAP_C_0402 24.7,81.2 r180 bottom value=0.1uF
C163 "Capacitor NP" CAP_C_0402 18.6,80.4 r180 bottom value=0.1uF
C164 "Capacitor NP" CAP_C_0402 20,83.6 r180 bottom value=0.1uF
C165 "Capacitor NP" CAP_C_0402 20,82.6 r180 bottom value=0.1uF
C166 "Capacitor NP" CAP_C_0402 23.5,84.1 r90 bottom value=0.1uF
C167 "Capacitor NP" CAP_C_0402 22.4,86.7 r0 bottom value=0.1uF
C168 "Capacitor NP" CAP_C_0402 22.575,81.125 r270 bottom value=0.1uF
C169 "Capacitor NP" CAP_C_0402 18.9,88.1 r270 bottom value=0.1uF
C170 "Capacitor NP" CAP_C_0402 13.575,81.3 r180 bottom value=0.1uF
C171 "Capacitor NP" CAP_C_0603 7,67.4 r90 top value=2.2uF
C172 "Capacitor NP" CAP_C_0603 9.6,68.4 r0 top value=2.2uF
C173 "Capacitor NP" CAP_C_0402 9.8,69.8 r0 top value=0.1uF
C174 "Capacitor NP" CAP_C_0402 12.675,102.525 r90 bottom value=0.1uF
C175 "Capacitor NP" CAP_C_0402 18.875,102.325 r180 bottom value=0.1uF
C176 "Capacitor NP" CAP_C_0402 28.8,105.77 r0 top value=0.1uF
C177 "Capacitor NP" CAP_C_0402 10.1,111.2 r0 bottom value=0.1uF
C178 "Capacitor NP" CAP_C_0402 10.1,105.4 r180 bottom value=0.1uF
C179 "Capacitor NP" CAP_C_0402 37.4,105.77 r0 top value=0.1uF
D1 "Diode Single" SOD-323 17.2,49 r270 top value=1N4148
D2 "Diode Schottky Dual CK" SOT-23-3 66.7,116.2 r0 top value=BAT54C
D3 "Diode Schottky" SOD-123 67.25,108.15 r90 top value=PMEG6010ER
D4 "LED DUAL 4 pin" LED_DUAL_SMD_2x1.25mm 124.9,26.3 r90 top value="RED, GREEN"
D5 "Diode Single" SOD-323 129.4,99.6 r0 top value=1N4148
D6 "Diode Single" SOD-323 137.3,99.6 r0 top value=1N4148
D7 "LED DUAL 4 pin" LED_DUAL_SMD_2x1.25mm 54.9,99.9 r0 top value="RED, GREEN"
D8 "Diode Single" SOD-323 14.45,92.025 r90 top value=1N4148
D9 "LED DUAL 4 pin" LED_DUAL_SMD_2x1.25mm 21.975,76.9 r270 top value="RED, GREEN"
FB1 "Ferrite Bead" IND_C_0603 22,30.2 r180 top value=180R
FB2 "Ferrite Bead" IND_C_0603 70.015,24 r180 bottom value=180R
FB3 "Ferrite Bead" IND_C_0603 79,14.7 r90 bottom value=180R
FB5 "Ferrite Bead" IND_C_0603 29.5,2.5 r180 bottom value=180R
FB6 "Ferrite Bead" IND_C_0603 55.1,31.1 r270 top value=180R
FB7 "Ferrite Bead" IND_C_0603 47.7,9.6 r0 bottom value=180R
FB8 "Ferrite Bead" IND_C_0603 45.8,31.1 r270 top value=180R
FB9 "Ferrite Bead" IND_C_0603 120.3,24.4 r270 top value=180R
FB10 "Ferrite Bead" IND_C_0603 127.7,105.4 r90 top value=180R
FB11 "Ferrite Bead" IND_C_0603 135.6,105.4 r90 top value=180R
FB12 "Ferrite Bead" IND_C_0603 103.5,121.7 r90 bottom value=180R
FB13 "Ferrite Bead" IND_C_0603 3.1,70.6 r90 top value=180R
J1 "CON JACK 2C 3P SPST" CON_JACK_POWER_TH_RA_MPD_EJ508A 10.7,40 r0 top value=2.1mm
J2 "Header 1x2" HDR_M_2.54_1x2 61.825,120.9 r90 top value="HDR-2.54 Male 1x2"
J3 "Header 1x2" HDR_M_2.54_1x2 45.325,120.92 r90 top value="HDR-2.54 Male 1x2"
J4 "CON SD CARD 11P_amphenol" 10067847-001RLF 132.35,50 r90 top locked value=SD
J5 "RJ45 J00-0045NL" J00-0045NL_RJ45_connector 68.6,10.9 r0 top value=RJ45
J6 "CON TERM BLK 1x5 TH Mount" CON_TERMINAL_3.81_1x5_TH_RA_PHO_1727049 113.5,121.444 r0 top locked value="TERMINAL 1x5"
J7 "CON USB2.0 Mini_Micro" CON_USB_MICRO-AB_SMD_TH_RA_FCI_10118194-0001LF 36.1,2.2 r180 top value="USB2.0 MICRO-B FEMALE"
J8 "CON USB2.0 A DUAL" CON_USB2.0-A_Dual_RCPT_TH_RA_AMN_AU-Y1008-2 50.5,13.79 r0 top value="USB2.0 STD-A DUAL FEMALE"
J9 "Header 1x3" HDR_F_2.54_1x3 116.6,24.06 r90 top value="HDR-2.54 Female 1x3"
J10 "Header 1x8" HDR_F_2.54_1X8 133.1,7.5 r0 top value="HDR-2.54 Female 1x8"
J11 "Header 1x3" HDR_M_2.54_1x3 128.2,119.9 r180 top value="HDR-2.54 Male 1x3"
J12 "Header 1x4" CON_TERMINAL_2.54_1x4_TH_RA_PHO_1725672 138.29,121.9 r180 top locked value="TERMINAL 1x4"
J13 "Header 1x2" HDR_M_2.54_1x2 58.525,120.92 r90 top value="HDR-2.54 Male 1x2"
J14 "SOCKET mikroBUS HOST" SOCKET_MIKROBUS_F_2.54_2X8_V_25.4X21 16.2,14.2 r90 top value="mikroBUS HOST"
J15 "CON FFC 1x50 Mount" CON_FFC_0.5_FEMALE_1X50_SMD_OMR_XF2M-5015-1A 89.25,102.5 r180 bottom locked value="FFC/FPC 50P Female"
J16 "Header 2x20" HDR_M_2.54_2x20 147.1,91.9 r270 top locked value="HDR-2.54 Male 2x20"
J17 "Header 2x15" HDR_M_2.54_2x15 83.4,121.8 r180 top locked
J18 "pads on PCB" CON_EDGE-CARD_PCB_RA_MEC1-108-02-F-D-RA1-SL 3.625,89.73 r270 top
J19 "Header 1x2" HDR_M_2.54_1x2 48.625,120.92 r90 top value="HDR-2.54 Male 1x2"
J20 "Header 1x2" HDR_M_2.54_1x2 51.925,120.92 r90 top value="HDR-2.54 Male 1x2"
J21 "Header 1x2" HDR_M_2.54_1x2 55.225,120.92 r90 top value="HDR-2.54 Male 1x2"
J22 "CON USB2.0 Mini_Micro" CON_USB_MICRO-AB_SMD_TH_RA_FCI_10118194-0001LF 2.426,64 r90 top value="USB2.0 MICRO-B FEMALE"
J23 "Header 2x10" HDR_M_2.54_2X10_S_TH_RA_OS_302-R201 26.63,113 r0 top
J24 "Header 1x6" HDR_M_2.54_1x6 4.4,110.8 r270 top value="HDR-2.54 Male 1x6"
L1 "Inductor" IND_C_1008 25.95,51.85 r90 top value=2.2uH
LABEL1 "LABEL_Need_Help_Large" LABEL_Need_Help_Large 125.425,63.85 r90 bottom value="Label Need Help Large"
LCD1 "TM5000 mechanical mockup" TM5000_mockup_model 33.02,46.44 r0 top locked value="LCD Display"
LD1 "LED_RGB_CLV1A" PLCC-4_CLV1A-FKB 100.5,20.8 r0 top value="RED, GREEN, BLUE"
PAD1 "Rubber Pad Cylindrical" "BUMP_ ESSENTRA_RBS-35_CYLINDRICAL_CLEAR_D9.50H4.8" 27,14.5 r180 bottom value="RUBBER PAD D9.5 H4.8"
PAD2 "Rubber Pad Cylindrical" "BUMP_ ESSENTRA_RBS-35_CYLINDRICAL_CLEAR_D9.50H4.8" 27,105 r180 bottom value="RUBBER PAD D9.5 H4.8"
PAD3 "Rubber Pad Cylindrical" "BUMP_ ESSENTRA_RBS-35_CYLINDRICAL_CLEAR_D9.50H4.8" 136,107 r180 bottom value="RUBBER PAD D9.5 H4.8"
PAD4 "Rubber Pad Cylindrical" "BUMP_ ESSENTRA_RBS-35_CYLINDRICAL_CLEAR_D9.50H4.8" 136,20 r180 bottom value="RUBBER PAD D9.5 H4.8"
Q1 "SIA923AEDJ-T1-GE3" "SIA923AEDJ PPAK_SC70_6L" 21.7,36.1 r0 top value=SIA923AEDJ
Q2 "SIA923AEDJ-T1-GE3" "SIA923AEDJ PPAK_SC70_6L" 21.8,33 r90 top value=SIA923AEDJ
Q3 "Transistor MOS-N GSD" SOT-23-3 8.5,51.9 r270 top value=TN2106
Q4 "Transistor MOS-N GSD" SOT-23-3 12.4,50.1 r270 top value=TN2106
Q5 "Transistor MOS-N GSD" SOT-23-3 12.4,53.7 r270 top value=TN2106
Q6 "Transistor MOS-P GSD" SOT-883 128,101.4 r90 top value=SSM3J56ACT
Q7 "Transistor MOS-N GSD" SOT-883 128,103.1 r90 top value=SSM3K56ACT
Q8 "Transistor MOS-P GSD" SOT-883 135.9,101.4 r90 top value=SSM3J56ACT
Q9 "Transistor MOS-N GSD" SOT-883 135.9,103.1 r90 top value=SSM3K56ACT
Q10 "Transistor MOS-N GSD" SOT-23-3 50.5,98 r270 top value=TN2106
Q11 "Transistor MOS-N GSD" SOT-23-3 50.5,101.7 r270 top value=TN2106
Q12 "Transistor MOS-N GSD" SOT-23-3 46.4,99 r270 top value=TN2106
Q13 "Transistor MOS-N GSD" SOT-23-3 100.1,26.7 r180 top value=TN2106
Q14 "Transistor MOS-N GSD" SOT-23-3 103.9,26.7 r180 top value=TN2106
Q15 "Transistor MOS-N GSD" SOT-23-3 96.3,26.7 r180 top value=TN2106
Q16 "Transistor MOS-N GSD" SOT-23-3 36.3,102.2 r270 bottom value=BSS138N
R1 "Shunt 4 Pin" RES_C_1206_SHUNT#1 27.3,34.8 r0 top value=0.01R
R2 "Resistor" RES_C_0402 17.8,36.7 r0 top value=100k
R3 "Resistor" RES_C_0402 17.8,34.3 r0 top value=100k
R4 "Resistor" RES_C_0402 33.2,52.9 r180 top value=10k
R5 "Resistor" RES_C_0402 17.8,33.1 r0 top value=100k
R6 "Resistor" RES_C_0402 30.7,39.5 r270 top value=100R
R7 "Shunt 4 Pin" RES_C_1206_SHUNT#1 28.25,60.35 r0 top value=0.01R
R8 "Shunt 4 Pin" RES_C_1206_SHUNT#1 29.375,65.6 r90 top value=0.01R
R9 "Shunt 4 Pin" RES_C_1206_SHUNT#1 20.8,65.6 r90 top value=0.01R
R10 "Shunt 4 Pin" RES_C_1206_SHUNT#2 21.95,60.35 r180 top value=0.01R
R11 "Resistor" RES_C_0402 19,49.665 r90 top value=20k
R12 "Resistor" RES_C_0402 26.1,69.85 r90 top value=10k
R13 "Resistor" RES_C_0402 27.9,69.8 r90 top value=10k
R14 "Resistor" RES_C_0603 22.8,65.75 r180 bottom value=8.45k
R15 "Resistor" RES_C_0402 9.2,49.4 r180 top value=100k
R16 "Resistor" RES_C_0402 13.1,47.6 r180 top value=100k
R17 "Resistor" RES_C_0402 13.1,56.2 r180 top value=100k
R18 "Resistor" RES_C_0402 9.6,54.8 r270 top value=1k
R19 "Resistor" RES_C_0402 7.4,54.8 r90 top value=10k
R20 "Resistor" RES_C_0402 67.3,112.4 r90 top value=100R
R21 "Resistor" RES_C_0402 67.8,84.8 r180 top value=1M
R22 "Resistor" RES_C_0402 74.5,86.2 r270 top value=0R
R23 "Resistor" RES_C_0402 69.7,79.9 r270 bottom value=5.62k
R24 "Resistor" RES_C_0402 71.2,83.7 r0 top value=1M
R25 "Resistor" RES_C_0201 75.5,69.725 r270 bottom value=10R
R26 "Resistor" RES_C_0402 103.1,89.5 r270 top value=0R
R27 "Resistor" RES_C_0402 67.25,83.25 r90 top value=0R
R28 "Resistor" RES_C_0402 69.25,83.25 r90 top value=0R
R29 "Resistor" RES_C_0402 20.6,48.05 r270 top value=100k
R30 "Resistor" RES_C_0402 66.475,77.225 r0 bottom value=0R
R31 "Resistor" RES_C_0402 92.8,81.5 r180 top value=22R
R32 "Resistor" RES_C_0402 92.8,82.5 r180 top value=22R
R33 "Resistor" RES_C_0402 33.2,54 r180 top value=10k
R34 "Resistor" RES_C_0402 34.4,58.1 r90 top value=100k
R35 "Resistor" RES_C_0402 35.5,58.1 r90 top value=100k
R36 "Resistor" RES_C_0402 38.75,58.1 r90 top value=100k
R37 "Resistor" RES_C_0402 39.85,58.1 r90 top value=100k
R38 "Resistor" RES_C_0402 92.8,81 r180 bottom value=22R
R39 "Resistor" RES_C_0402 92.8,80 r180 bottom value=22R
R40 "Resistor" RES_C_0402 92.8,79.5 r180 top value=22R
R41 "Resistor" RES_C_0402 92.8,80.5 r180 top value=22R
R42 "Resistor" RES_C_0402 92.8,79 r180 bottom value=22R
R43 "Resistor" RES_C_0402 92.8,78 r180 bottom value=22R
R44 "Resistor" RES_C_0402 92.8,75.5 r180 top value=22R
R45 "Resistor" RES_C_0402 92.8,76.5 r180 top value=22R
R46 "Resistor" RES_C_0402 92.8,71 r180 bottom value=22R
R47 "Resistor" RES_C_0402 36.569,58.106 r270 top value=100k
R48 "Resistor" RES_C_0402 37.65,58.1 r270 top value=100k
R49 "Resistor" RES_C_0402 40.95,58.1 r270 top value=100k
R50 "Resistor" RES_C_0402 92.801,72 r180 bottom value=22R
R51 "Resistor" RES_C_0402 92.801,69 r180 bottom value=22R
R52 "Resistor" RES_C_0402 92.801,71.5 r180 top value=22R
R53 "Resistor" RES_C_0402 92.801,70.5 r180 top value=22R
R54 "Resistor" RES_C_0402 92.801,72.5 r180 top value=22R
R55 "Resistor" RES_C_0402 92.8,76 r180 bottom value=22R
R56 "Resistor" RES_C_0402 92.8,77 r180 bottom value=22R
R57 "Resistor" RES_C_0402 92.8,74 r180 bottom value=22R
R58 "Resistor" RES_C_0402 92.801,68.5 r180 top value=22R
R59 "Resistor" RES_C_0402 92.801,69.5 r180 top value=22R
R60 "Resistor" RES_C_0402 92.8,60.5 r0 bottom value=0R
R61 "Resistor" RES_C_0402 92.8,87 r0 bottom value=2.2k
R62 "Resistor" RES_C_0402 92.8,86.5 r0 top value=2.2k
R63 "Resistor" RES_C_0402 92.8,62 r0 bottom value=0R
R64 "Resistor" RES_C_0402 92.8,85.5 r0 top value=22R
R65 "Resistor" RES_C_0402 84.4,61.1 r0 top value=0R
R66 "Resistor" RES_C_0402 84.4,63.1 r0 top value=0R
R67 "Resistor" RES_C_0402 92.8,84.5 r0 top value=22R
R68 "Resistor" RES_C_0402 92.8,83.5 r0 top value=22R
R69 "Resistor" RES_C_0402 82.5,60.6 r180 top value=22R
R70 "Resistor" RES_C_0402 82.5,59.6 r180 top value=22R
R71 "Resistor" RES_C_0402 84.4,59.1 r180 top value=22R
R72 "Resistor" RES_C_0402 84.4,58.1 r180 top value=22R
R73 "Resistor" RES_C_0402 92.8,86 r0 bottom value=22R
R74 "Resistor" RES_C_0402 84.4,56.1 r180 top value=22R
R75 "Resistor" RES_C_0402 84.4,55.1 r180 top value=22R
R76 "Resistor" RES_C_0402 92.8,85 r0 bottom value=22R
R77 "Resistor" RES_C_0402 82.5,54.6 r180 top value=22R
R78 "Resistor" RES_C_0402 92.8,84 r0 bottom value=22R
R79 "Resistor" RES_C_0402 82.5,53.6 r180 top value=22R
R80 "Resistor" RES_C_0402 82.5,57.6 r180 top value=22R
R81 "Resistor" RES_C_0402 82.5,56.6 r180 top value=22R
R82 "Resistor" RES_C_0402 84.4,53.1 r180 top value=22R
R83 "Resistor" RES_C_0402 45.7,50.5 r180 top value=2.2k
R84 "Resistor" RES_C_0402 45.7,55.5 r180 top value=2.2k
R85 "Resistor" RES_C_0402 84.4,52.1 r180 top value=22R
R86 "Resistor" RES_C_0402 85.05,26.9 r90 top value=22R
R87 "Resistor" RES_C_0402 45.7,54.5 r180 top value=22R
R88 "Resistor" RES_C_0402 84.05,26.9 r90 top value=22R
R89 "Resistor" RES_C_0402 45.7,52.5 r180 top value=22R
R90 "Resistor" RES_C_0402 45.7,51.5 r180 top value=22R
R91 "Resistor" RES_C_0402 68.25,83.25 r90 top value=0R
R92 "Resistor" RES_C_0402 45.7,53.5 r180 top value=22R
R93 "Resistor" RES_C_0402 45.7,49.5 r180 top value=22R
R94 "Resistor" RES_C_0402 45.7,47.5 r180 top value=22R
R95 "Resistor" RES_C_0402 45.7,46.5 r180 top value=22R
R96 "Resistor" RES_C_0402 45.7,48.5 r180 top value=22R
R97 "Resistor" RES_C_0402 104,84.8 r0 top value=10k
R98 "Resistor" RES_C_0402 104,87.8 r0 top value=10k
R99 "Resistor" RES_C_0402 88.8,46.3 r270 bottom value=10k
R100 "Resistor" RES_C_0402 90.1,46.3 r270 bottom value=10k
R101 "Resistor" RES_C_0402 88.7,53.6 r270 bottom value=10k
R102 "Resistor" RES_C_0402 90.1,53.6 r270 bottom value=10k
R103 "Resistor" RES_C_0402 87.5,46.3 r270 bottom value=10k
R104 "Resistor" RES_C_0402 104,86.8 r0 top value=10k
R105 "Resistor" RES_C_0402 104,85.8 r0 top value=10k
R106 "Resistor" RES_C_0402 93,53.3 r270 bottom value=10k
R107 "Resistor" RES_C_0402 116.95,36.95 r90 top value=10k
R108 "Resistor" RES_C_0402 117.5,52.4 r180 top value=10k
R109 "Resistor" RES_C_0402 117.5,54 r180 top value=10k
R110 "Resistor" RES_C_0402 117.5,39.9 r180 top value=10k
R111 "Resistor" RES_C_0402 117.5,41.6 r180 top value=10k
R112 "Resistor" RES_C_0402 117.5,56.5 r180 top value=10k
R113 "Resistor" RES_C_0402 117.5,59 r180 top value=10k
R114 "Resistor" RES_C_0402 43.7,90 r90 top value=10k
R115 "Resistor" RES_C_0402 44.8,89.7 r90 top value=10k
R116 "Resistor" RES_C_0402 38.2,89.7 r90 top value=10k
R117 "Resistor" RES_C_0402 39.3,89.7 r270 top value=10k
R118 "Resistor" RES_C_0402 117.95,36.95 r270 top value=10k
R119 "Resistor" RES_C_0402 72.825,63.4 r90 top value=20k
R120 "Resistor" RES_C_0201 60.05,60.3 r90 bottom value=4.7k
R121 "Resistor" RES_C_0201 61.6,60.3 r270 bottom value=4.7k
R122 "Resistor" RES_C_0402 73.3,30.8 r270 top value=1k
R123 "Resistor" RES_C_0402 79.2,28.7 r180 top value=1k
R124 "Resistor" RES_C_0402 78.415,27.2 r180 top value=6.49k
R125 "Resistor" RES_C_0402 73.2,8.075 r270 bottom value=470R
R126 "Resistor" RES_C_0402 78.715,23.3 r270 top value=0R
R127 "Resistor" RES_C_0402 75.115,30.8 r90 top value=10k
R128 "Resistor" RES_C_0402 77.715,23.3 r270 top value=0R
R129 "Resistor" RES_C_0402 72.075,8.075 r270 bottom value=10k
R130 "Resistor" RES_C_0402 71.015,25.7 r180 top value=0R
R131 "Resistor" RES_C_0402 66.7,14.5 r90 bottom value=0R
R132 "Resistor" RES_C_0402 78.415,25.15 r180 top value=51R
R133 "Resistor" RES_C_0402 78.415,26.15 r0 top value=0R
R134 "Resistor" RES_C_1210 106.275,117.55 r90 bottom value=62R
R135 "Resistor" RES_C_0402 110.7,108.3 r180 top value=0R
R136 "Resistor" RES_C_1210 109.275,117.55 r270 bottom value=62R
R137 "Resistor" RES_C_1210 117.725,117.55 r90 bottom value=62R
R138 "Resistor" RES_C_0402 122.1,108.3 r180 top value=0R
R139 "Resistor" RES_C_1210 120.725,117.55 r270 bottom value=62R
R140 "Resistor" RES_C_0402 92.8,83 r180 bottom value=22R
R141 "Resistor" RES_C_0402 92.8,74.5 r180 top value=22R
R142 "Resistor" RES_C_0402 92.8,77.5 r180 top value=22R
R143 "Resistor" RES_C_0402 92.8,67.5 r180 bottom value=22R
R144 "Resistor" RES_C_0402 92.8,82 r180 bottom value=22R
R145 "Resistor" RES_C_0402 92.8,73.5 r180 top value=22R
R146 "Resistor" RES_C_0402 92.8,78.5 r180 top value=22R
R147 "Resistor" RES_C_0402 92.8,66.5 r180 bottom value=22R
R148 "Resistor" RES_C_0402 35,29.075 r90 top value=100k
R149 "Resistor" RES_C_0402 64.338,85.188 r90 top value=51R
R150 "Resistor" RES_C_0402 35,31.475 r270 top value=200k
R152 "Resistor" RES_C_0402 56.636,41.404 r90 top value=10k
R153 "Resistor" RES_C_0402 57.875,41.4 r270 top value=10k
R154 "Resistor" RES_C_0402 47.53,41.31 r90 top value=10k
R155 "Resistor" RES_C_0402 48.83,41.31 r270 top value=10k
R156 "Resistor" RES_C_0402 85.5,37.8 r180 top value=22R
R157 "Resistor" RES_C_0402 85.5,36.8 r180 top value=22R
R158 "Resistor" RES_C_0402 85.4,41.6 r180 top value=22R
R159 "Resistor" RES_C_0402 85.4,40.6 r180 top value=22R
R160 "Resistor" RES_C_0402 124.3,29.5 r90 top value=1k
R161 "Resistor" RES_C_0402 125.5,29.5 r90 top value=1k
R162 "Resistor" RES_C_0402 118.65,18.7 r180 top value=100k
R163 "Resistor" RES_C_0402 132,11.9 r270 bottom value=100k
R164 "Resistor" RES_C_0402 130.8,11.9 r270 bottom value=100k
R165 "Resistor" RES_C_0402 129.6,11.9 r270 bottom value=100k
R166 "Resistor" RES_C_0402 127.5,13 r0 bottom value=100k
R167 "Resistor" RES_C_0402 127.5,14.2 r0 bottom value=100k
R168 "Resistor" RES_C_0402 125.5,11 r90 bottom value=10k
R169 "Resistor" RES_C_0402 135.6,29.1 r90 top value=0R
R170 "Resistor" RES_C_0402 134.4,29.1 r90 top value=0R
R171 "Resistor" RES_C_0402 133.2,29.1 r90 top value=0R
R172 "Resistor" RES_C_0402 122.3,16.15 r270 top value=51R
R173 "Resistor" RES_C_0402 132,29.1 r90 top value=0R
R174 "Resistor" RES_C_0402 143.1,28.2 r0 top value=0R
R175 "Resistor" RES_C_0402 121,16.15 r270 top value=51R
R176 "Resistor" RES_C_0402 128.8,98 r0 top value=10k
R177 "Resistor" RES_C_0402 128.375,94.35 r90 top value=0R
R178 "Resistor" RES_C_0402 131.9,101.6 r90 top value=0R
R179 "Resistor" RES_C_0402 131.9,103.7 r270 top value=10k
R180 "Resistor" RES_C_0402 136.6,98 r0 top value=10k
R181 "Resistor" RES_C_0402 134.9,97.55 r90 top value=0R
R182 "Resistor" RES_C_0402 139.8,101.6 r90 top value=0R
R183 "Resistor" RES_C_0402 139.8,103.7 r270 top value=10k
R185 "Resistor" RES_C_0402 104.1,91.5 r270 top value=100R
R186 "Resistor" RES_C_0402 60.7,29.4 r0 bottom value=10k
R187 "Resistor" RES_C_0402 55,98 r0 top value=1k
R188 "Resistor" RES_C_0402 55,101.8 r0 top value=1k
R189 "Resistor" RES_C_0402 47.2,101.5 r180 top value=100k
R190 "Resistor" RES_C_0402 104.1,89.5 r90 top value=100R
R191 "Resistor" RES_C_0402 103.1,91.5 r270 top value=100R
R192 "Resistor" RES_C_0402 62.7,29.4 r180 bottom value=100R
R194 "Resistor" RES_C_0402 72.2,98 r0 top value=100k
R195 "Resistor" RES_C_0402 84.4,62.1 r0 top value=100R
R196 "Resistor" RES_C_0402 100.1,29.3 r180 top value=10k
R197 "Resistor" RES_C_0402 70.2,98 r0 top value=100R
R199 "Resistor" RES_C_0402 100.7,23.7 r270 top value=1k
R200 "Resistor" RES_C_0402 92.8,62.9 r0 bottom value=100R
R201 "Resistor" RES_C_0402 101.9,23.7 r270 top value=1k
R202 "Resistor" RES_C_0402 103.9,29.3 r180 top value=10k
R203 "Resistor" RES_C_0402 97.9,23.7 r270 top value=2.2k
R204 "Resistor" RES_C_0402 113.9,14.5 r180 bottom value=100k
R206 "Resistor" RES_C_0402 92.8,59.5 r0 bottom value=100R
R207 "Resistor" RES_C_0402 96.3,29.3 r180 top value=10k
R208 "Resistor" RES_C_0402 93.7,94.7 r90 bottom value=0R
R209 "Resistor" RES_C_0402 94.5,91.6 r90 bottom value=0R
R210 "Resistor" RES_C_0402 95.5,94.7 r90 bottom value=0R
R211 "Resistor" RES_C_0402 96.3,91.7 r90 bottom value=0R
R212 "Resistor" RES_C_0402 88,102.8 r90 top value=22R
R213 "Resistor" RES_C_0402 96.6,102.8 r270 top value=22R
R214 "Resistor" RES_C_0402 101.2,98.6 r0 bottom value=0R
R215 "Resistor" RES_C_0402 87,100.659 r270 top value=22R
R216 "Resistor" RES_C_0402 86,100.659 r270 top value=22R
R217 "Resistor" RES_C_0402 101.2,97.5 r0 bottom value=0R
R218 "Resistor" RES_C_0402 86.5,102.8 r270 top value=22R
R219 "Resistor" RES_C_0402 85.5,102.8 r270 top value=22R
R220 "Resistor" RES_C_0402 78,100.659 r270 top value=22R
R221 "Resistor" RES_C_0402 78.5,102.8 r90 top value=22R
R222 "Resistor" RES_C_0402 79,100.659 r270 top value=22R
R223 "Resistor" RES_C_0402 79.5,102.8 r90 top value=22R
R224 "Resistor" RES_C_0402 80.5,102.8 r270 top value=22R
R225 "Resistor" RES_C_0402 81,100.659 r90 top value=22R
R226 "Resistor" RES_C_0402 81.5,102.8 r270 top value=22R
R227 "Resistor" RES_C_0402 82,100.659 r90 top value=22R
R228 "Resistor" RES_C_0402 83,100.659 r270 top value=22R
R229 "Resistor" RES_C_0402 83.5,102.8 r90 top value=22R
R230 "Resistor" RES_C_0402 84,100.659 r270 top value=22R
R231 "Resistor" RES_C_0402 84.5,102.8 r90 top value=22R
R232 "Resistor" RES_C_0402 50.225,118.195 r0 bottom value=10k
R233 "Resistor" RES_C_0402 24.475,90.2 r0 top value=0R
R234 "Resistor" RES_C_0402 22.475,91.3 r0 top value=100R
R235 "Resistor" RES_C_0402 11.175,89.6 r180 top value=100R
R236 "Resistor" RES_C_0402 22.475,90.2 r180 top value=150R
R237 "Resistor" RES_C_0402 12.9,92.2 r270 top value=10k
R238 "Resistor" RES_C_0402 13.125,89.6 r180 top value=100R
R239 "Resistor" RES_C_0402 19.975,91.3 r270 top value=0R
R240 "Resistor" RES_C_0402 16.075,78 r90 top value=6.8k
R241 "Resistor" RES_C_0402 25.975,90.4 r270 top value=10k
R242 "Resistor" RES_C_0402 27.375,85.7 r270 top value=150R
R243 "Resistor" RES_C_0402 28.475,85.7 r270 top value=150R
R244 "Resistor" RES_C_0402 24.975,85.6 r180 bottom value=150R
R245 "Resistor" RES_C_0402 20.975,91.3 r270 top value=100k
R246 "Resistor" RES_C_0402 22.575,73.7 r90 top value=1k
R247 "Resistor" RES_C_0402 21.05,79.8 r270 bottom value=39R
R248 "Resistor" RES_C_0402 20.05,79.8 r270 bottom value=39R
R249 "Resistor" RES_C_0402 21.475,73.7 r90 top value=1k
R250 "Resistor" RES_C_0402 27.875,83.5 r0 top value=10k
R251 "Resistor" RES_C_0402 10.8,80.625 r0 top value=51R
R252 "Resistor" RES_C_0402 16.875,105.025 r270 bottom value=22R
R254 "Resistor" RES_C_0402 14.275,105.025 r270 bottom value=22R
R256 "Resistor" RES_C_0402 19.9,109.6 r180 top value=100k
R257 "Resistor" RES_C_0402 23.9,109.6 r0 top value=100k
R258 "Resistor" RES_C_0402 21.9,109.6 r180 top value=100k
R259 "Resistor" RES_C_0402 31.5,109.6 r0 top value=100k
R260 "Resistor" RES_C_0402 35.5,109.6 r0 top value=100k
R261 "Resistor" RES_C_0402 1.4,104.4 r0 bottom value=100k
R262 "Resistor" RES_C_0402 1.4,114.6 r0 bottom value=100k
R263 "Resistor" RES_C_0402 1.4,107 r180 bottom value=100k
R264 "Resistor" RES_C_0402 1.4,109.5 r180 bottom value=100k
R265 "Resistor" RES_C_0402 33.5,109.6 r180 top value=100R
R266 "Resistor" RES_C_0402 12.7,107 r180 bottom value=22R
R268 "Resistor" RES_C_0402 12.7,109.6 r180 bottom value=22R
R270 "Resistor" RES_C_0402 34.7,100.1 r0 bottom value=100k
SW1 "Switch 4 Pin" SW_SMD_6mmX6mm_TL3301 82.3,6.5 r270 top value="TACT SPST"
SW2 "Switch 4 Pin" SW_SMD_6mmX6mm_TL3301 92.4,6.5 r270 top value="TACT SPST"
SW3 "Switch 4 Pin" SW_SMD_6mmX6mm_TL3301 102.5,6.5 r270 top value="TACT SPST"
SW4 "Switch 4 Pin" SW_SMD_6mmX6mm_TL3301 112.6,6.5 r270 top value="TACT SPST"
TP1 "GND" CON_TP_TH_V_BLK_KEC_5011 4,32 r0 top value="TP LOOP Black TH"
TP2 "SMD Test Point" TP_1x1_SMD#1 65.75,83.75 r90 top
TP4 "SMD Test Point" TP_1x1_SMD#2 79.975,23.8 r180 top
TP5 "SMD Test Point" TP_1x1_SMD#1 93.2,89.3 r90 top
TP6 "SMD Test Point" TP_1x1_SMD#1 94.5,89.3 r90 top
TP7 "SMD Test Point" TP_1x1_SMD#1 95.8,89.3 r90 top
TP8 "SMD Test Point" TP_1x1_SMD#1 97.1,89.3 r90 top
TP9 "SMD Test Point" TP_1x1_SMD#1 16.4,80.4 r90 top
TP10 "SMD Test Point" TP_1x1_SMD#3 0.825,104.4 r90 top
TP11 "SMD Test Point" TP_1x1_SMD#1 1,114.6 r90 top
U1 "NCP349 DFN-6" DFN-6_2x1.6_EP0.4x0.35 16.9,38.6 r270 top value=NCP349MNAETBG
U2 "PAC1710 DFN-10" DFN-10_3x3 28.2,39.1 r90 top value=PAC1710
U3 "MIC2800 VFQFN-16" QFN-16_3X3 22.031,51.818 r90 top value=MIC2800-G8SYML-TR
U4 "PAC1934 UQFN-16" UQFN-16_4X4_EP2.6X2.6 25.1,66.25 r270 top value=PAC1934
U5 "SAM9X60 TFBGA-228" "SAM9X60 TFBGA-228" 72.5,73 r180 top locked value=SAM9X60-V/DWB
U6 "MCP23008 QFN-20" QFN-20_4x4 37.15,53.45 r270 top value=MCP23008
U7 "24XXXX SOT-23-6" SOT-23-6 100.7,85.6 r270 top value=24AA025E48
U8 "SST26VFXXX SOIC-8_WSON-8_SOIJ-8" SOIJ-8 89.4,49.9 r270 top value=SST26VF064B
U9 "MT29F4G08ABA TSOP-48" TSOP-48_P0.5 42,78 r270 top locked value="MT29F4G08ABAEAWP:E TR"
U10 "W972GG6KB-25 WBGA-84" WBGA-84_P0.8_8x12.5x1.2 56.375,56 r270 top locked value=W972GG6KB-25
U11 "ETHERNET QFN-24" QFN-24_4X4 74.685,27 r90 top value=KSZ8081RNAIA-TR
U12 "MCP2542 DFN-8" DFN-8_3x3_EP2.4X1.55 107.8,106.7 r0 top value=MCP2542
U13 "MCP2542 DFN-8" DFN-8_3x3_EP2.4X1.55 119.2,106.7 r0 top value=MCP2542
U14 "NL27WZ125 US-8" US-8 117.5,88 r90 top value=NL27WZ125USG
U15 "NL27WZ125 US-8" US-8 112,87.79 r90 top value=NL27WZ125USG
U16 "NL27WZ126 US-8" US-8 121.5,88 r90 top value=NL27WZ126USG
U17 "NL27WZ126 US-8" US-8 108.2,87.8 r90 top value=NL27WZ126USG
U19 "MIC2025-1YM" SOIC-8 56,36.4 r270 top value="USB Power Switch"
U20 "MIC2025-1YM" SOIC-8 46.9,36.4 r270 top value="USB Power Switch"
U21 "NL27WZ125 US-8" US-8 88.8,37.269 r0 top value=NL27WZ125USG
U22 "MCP172X FIX DFN-8" DFN-8_2x3 119.7,28 r180 top value=MCP1725/3.3V
U23 "NL27WZ126 US-8" US-8 88.711,41.15 r0 top value=NL27WZ126USG
U24 "MODULE ATWILC3000-MR110CA" "MODULE ATWILC3000-MR110CA" 135.95,19 r270 top value=ATWILC3000-MR110CA
U25 "74HC1G126SE-7" SC-70-5#1 44.4,85.275 r180 bottom value=74AHC1G126
U26 "74HC1G126SE-7" SC-70-5#2 94.325,53.3 r90 top value=74AHC1G126
U27 "ATSAM3U4CA-CU TFBGA-100" TFBGA-100_P0.8_9X9X1.1 21.875,84.4 r90 top locked value=ATSAM3U4CA-CU
U28 "MIC5528MT DFN-6" DFN-6_1.2X1.2 8.9,66.6 r90 top value="MIC5528 3V3"
U29 "TXS0102" US-8 15.6,102.625 r0 bottom
U30 "TXS0102" US-8 10.1,108.3 r270 bottom
U31 "IDTQS3VH257 TSSOP-16" TSSOP-16 25.8,102.37 r0 top value=IDTQS3VH257PAG
U32 "IDTQS3VH125 SSOP-16" QSOP-16 34.7,102.37 r0 top value=IDTQS3VH125
VBUS_JLINK "SMD Test Point" TP_1x1_SMD#1 7,65.3 r180 top
VBUS_USBA "SMD Test Point" TP_1x1_SMD#1 34.8,18.2 r90 top
VBUS_USBB "SMD Test Point" TP_1x1_SMD#1 40.5,18.2 r90 top
VBUS_USBC "SMD Test Point" TP_1x1_SMD#1 37.9,18.2 r0 top
VDD_3V3 "SMD Test Point" TP_1x1_SMD#1 32.5,77.65 r270 top
VDD_3V3_3U "SMD Test Point" TP_1x1_SMD#1 11.8,68.3 r180 top
VDD_MAIN_5V "SMD Test Point" TP_1x1_SMD#1 26.6,45.6 r180 top
VDD_WILC "SMD Test Point" TP_1x1_SMD#1 116.6,18.7 r90 top
VDDCORE "SMD Test Point" TP_1x1_SMD#1 34.575,74.775 r270 top
VDDIOM "SMD Test Point" TP_1x1_SMD#1 32.275,61.475 r0 top
Y1 "Crystal 4 Pins" CRYSTAL_ABM8G 67.4,88.7 r270 top value=24MHz
Y2 "Crystal 2 Pins" CRYSTAL_ABS06 71.2,86.4 r0 top value=32.768Khz
Y3 "DSC10xx DFN-4" CDFN-4_3.2X2.5 63.388,88.388 r0 top value=24MHz
Y5 "Crystal 4 pins 1-3" CRYSTAL_L3.2W2.5H0.8 79.915,20.3 r180 top value=25MHz
Y6 "OSCILLATOR 4 Pins" "DFN-4_VFLGA_1.6 X 1.2" 82.95,24.525 r90 top value=DSC6102HI2B-025.000
Y7 "OSCILLATOR ASH7KW" OSCILLATOR_ASH7KW_L3.2W1.5H1 123.2,12.95 r0 top value=32.768kHz
Y8 "OSC_DSC6083CE2A_3225" OSCILLATOR_DSC1001_L3.2W2.5H0.85 119.9,13.35 r180 top value=32.768Hz
Y9 "Crystal 4 Pins" CRYSTAL_L7.5W5.2H1.4 11.175,82.7 r0 top value=12MHz
Y10 "OSCILLATOR DSC60XX" OSCILLATOR_DSC60000L2.5W2.0H0.89 11.175,82.7 r180 top value="12.00 MHz"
